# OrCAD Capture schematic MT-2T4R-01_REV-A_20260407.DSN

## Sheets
1 PAGE01.Cheetah PWR: size A3; title: MT-2T4R; rev: A; note: Cheetah PWR
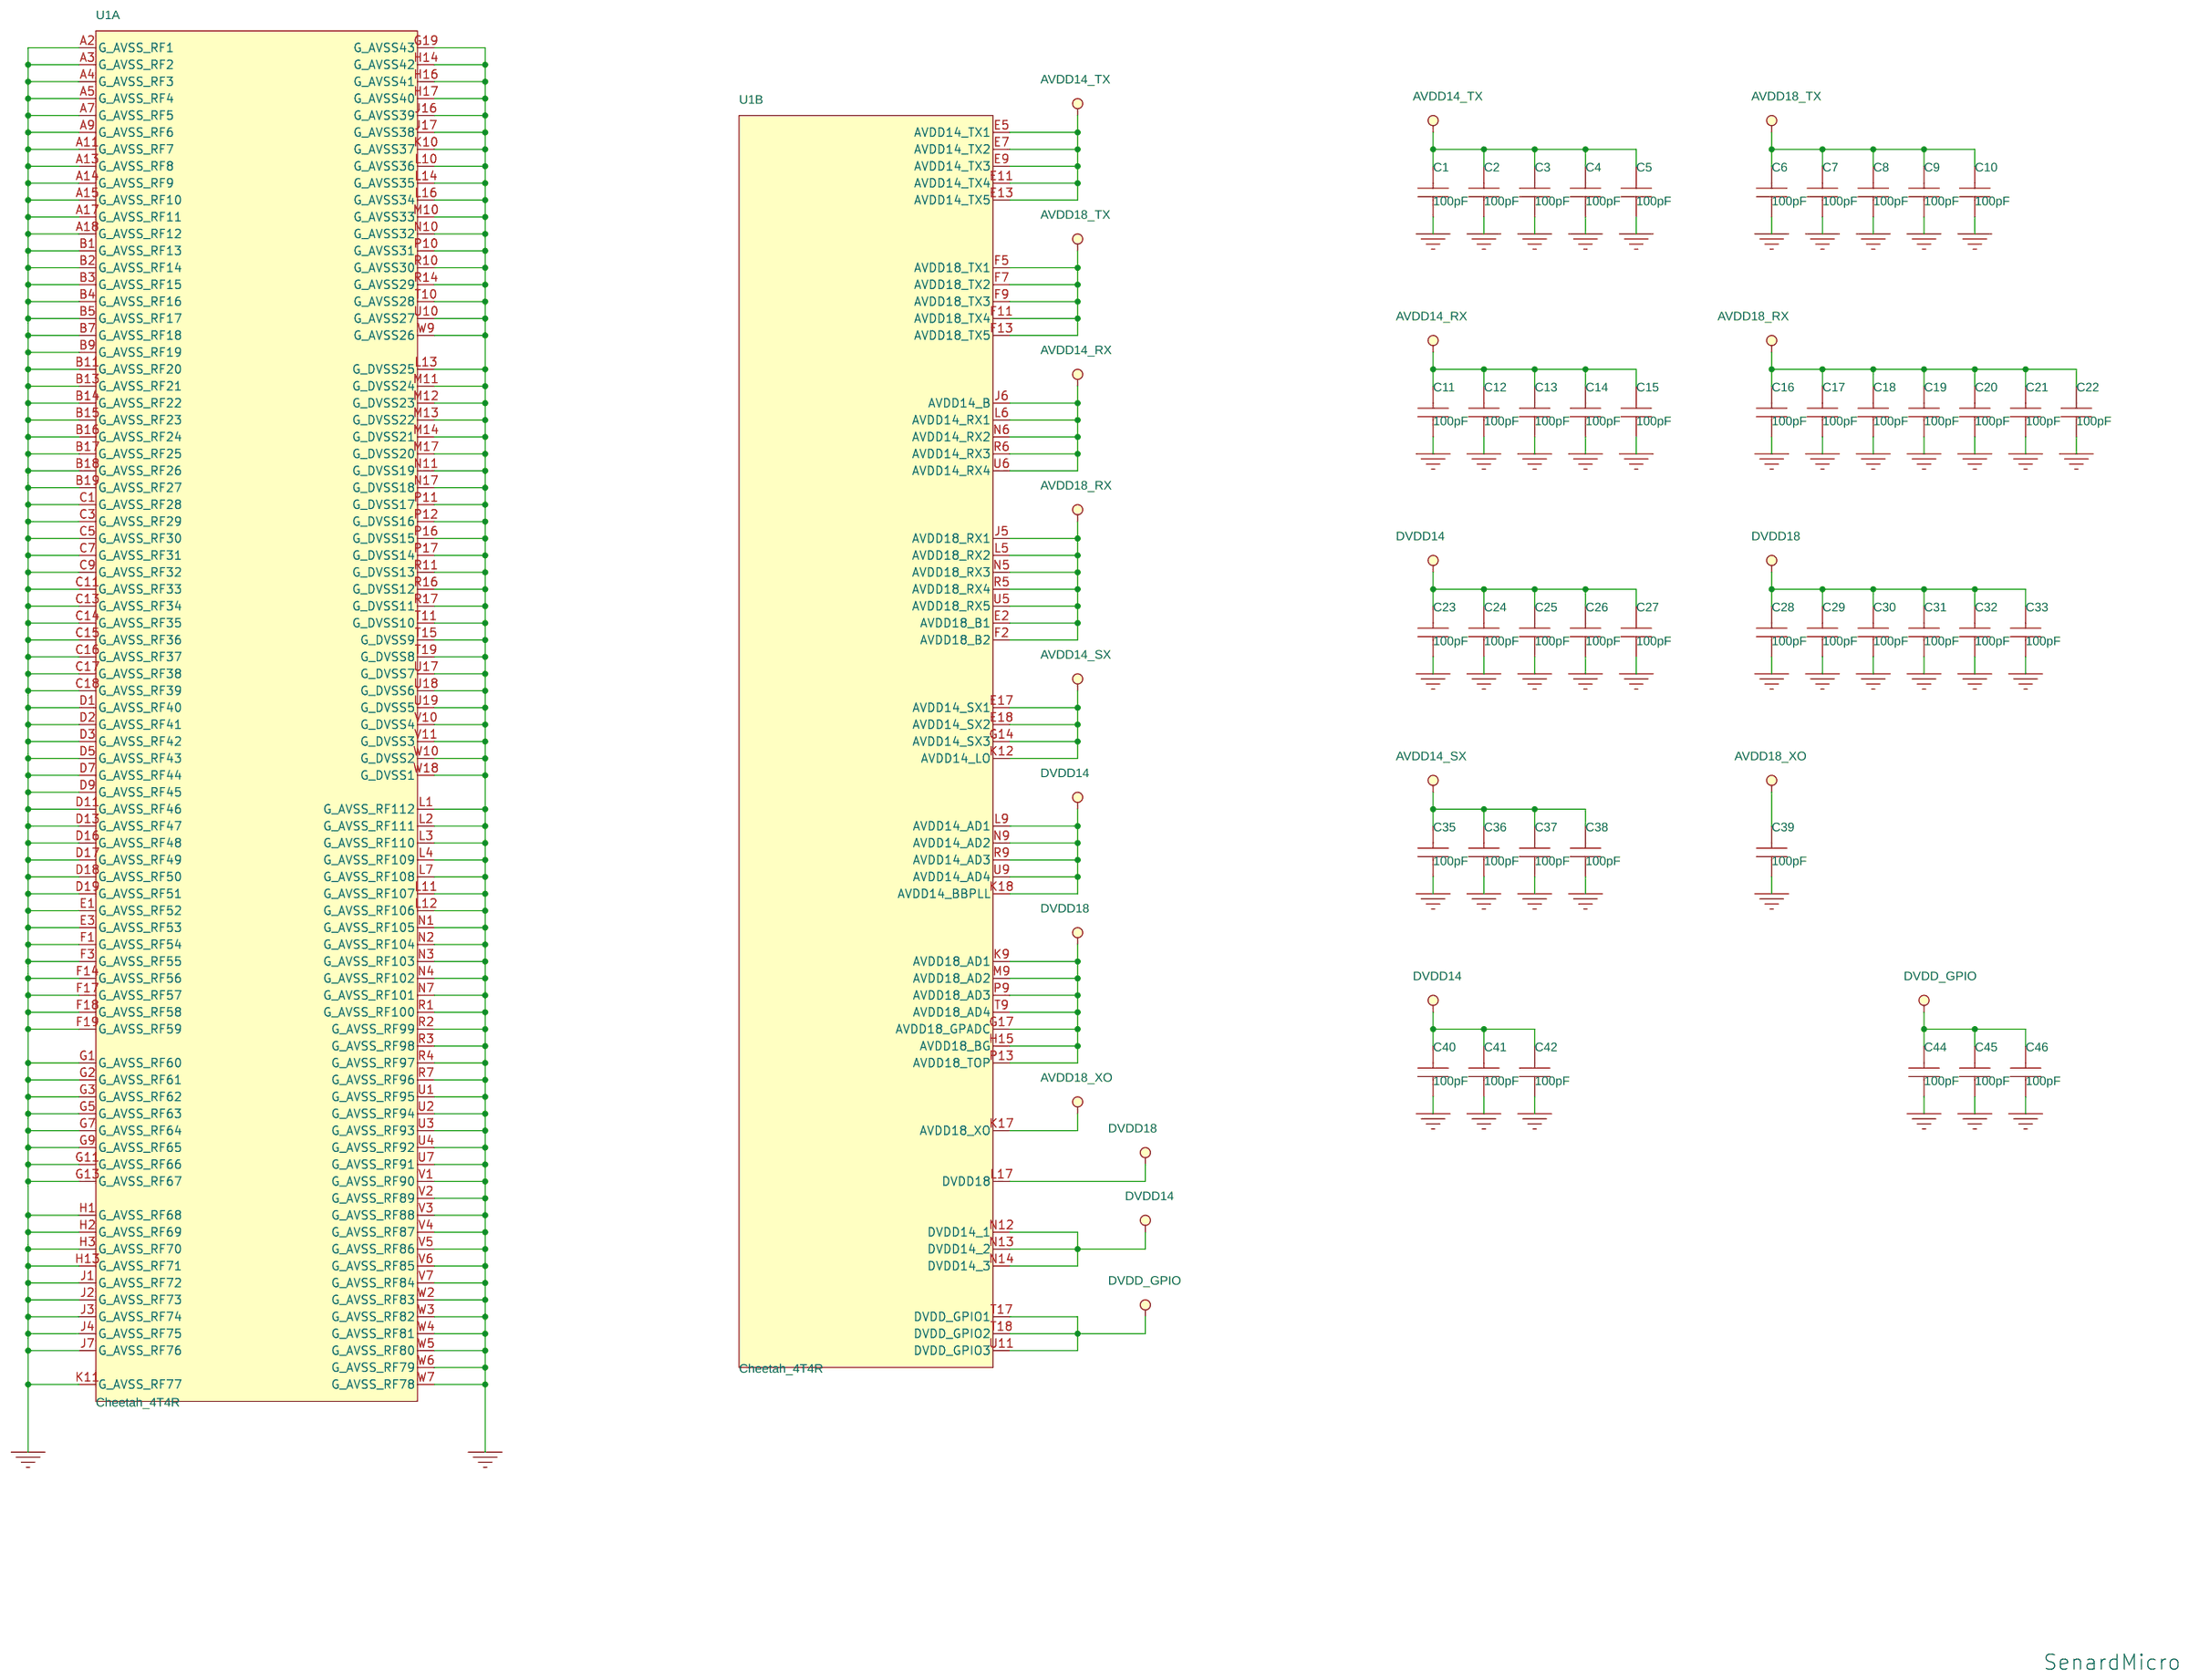
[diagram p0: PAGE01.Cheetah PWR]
2 PAGE02.Cheetah IO: size A3; note: Cheetah IO
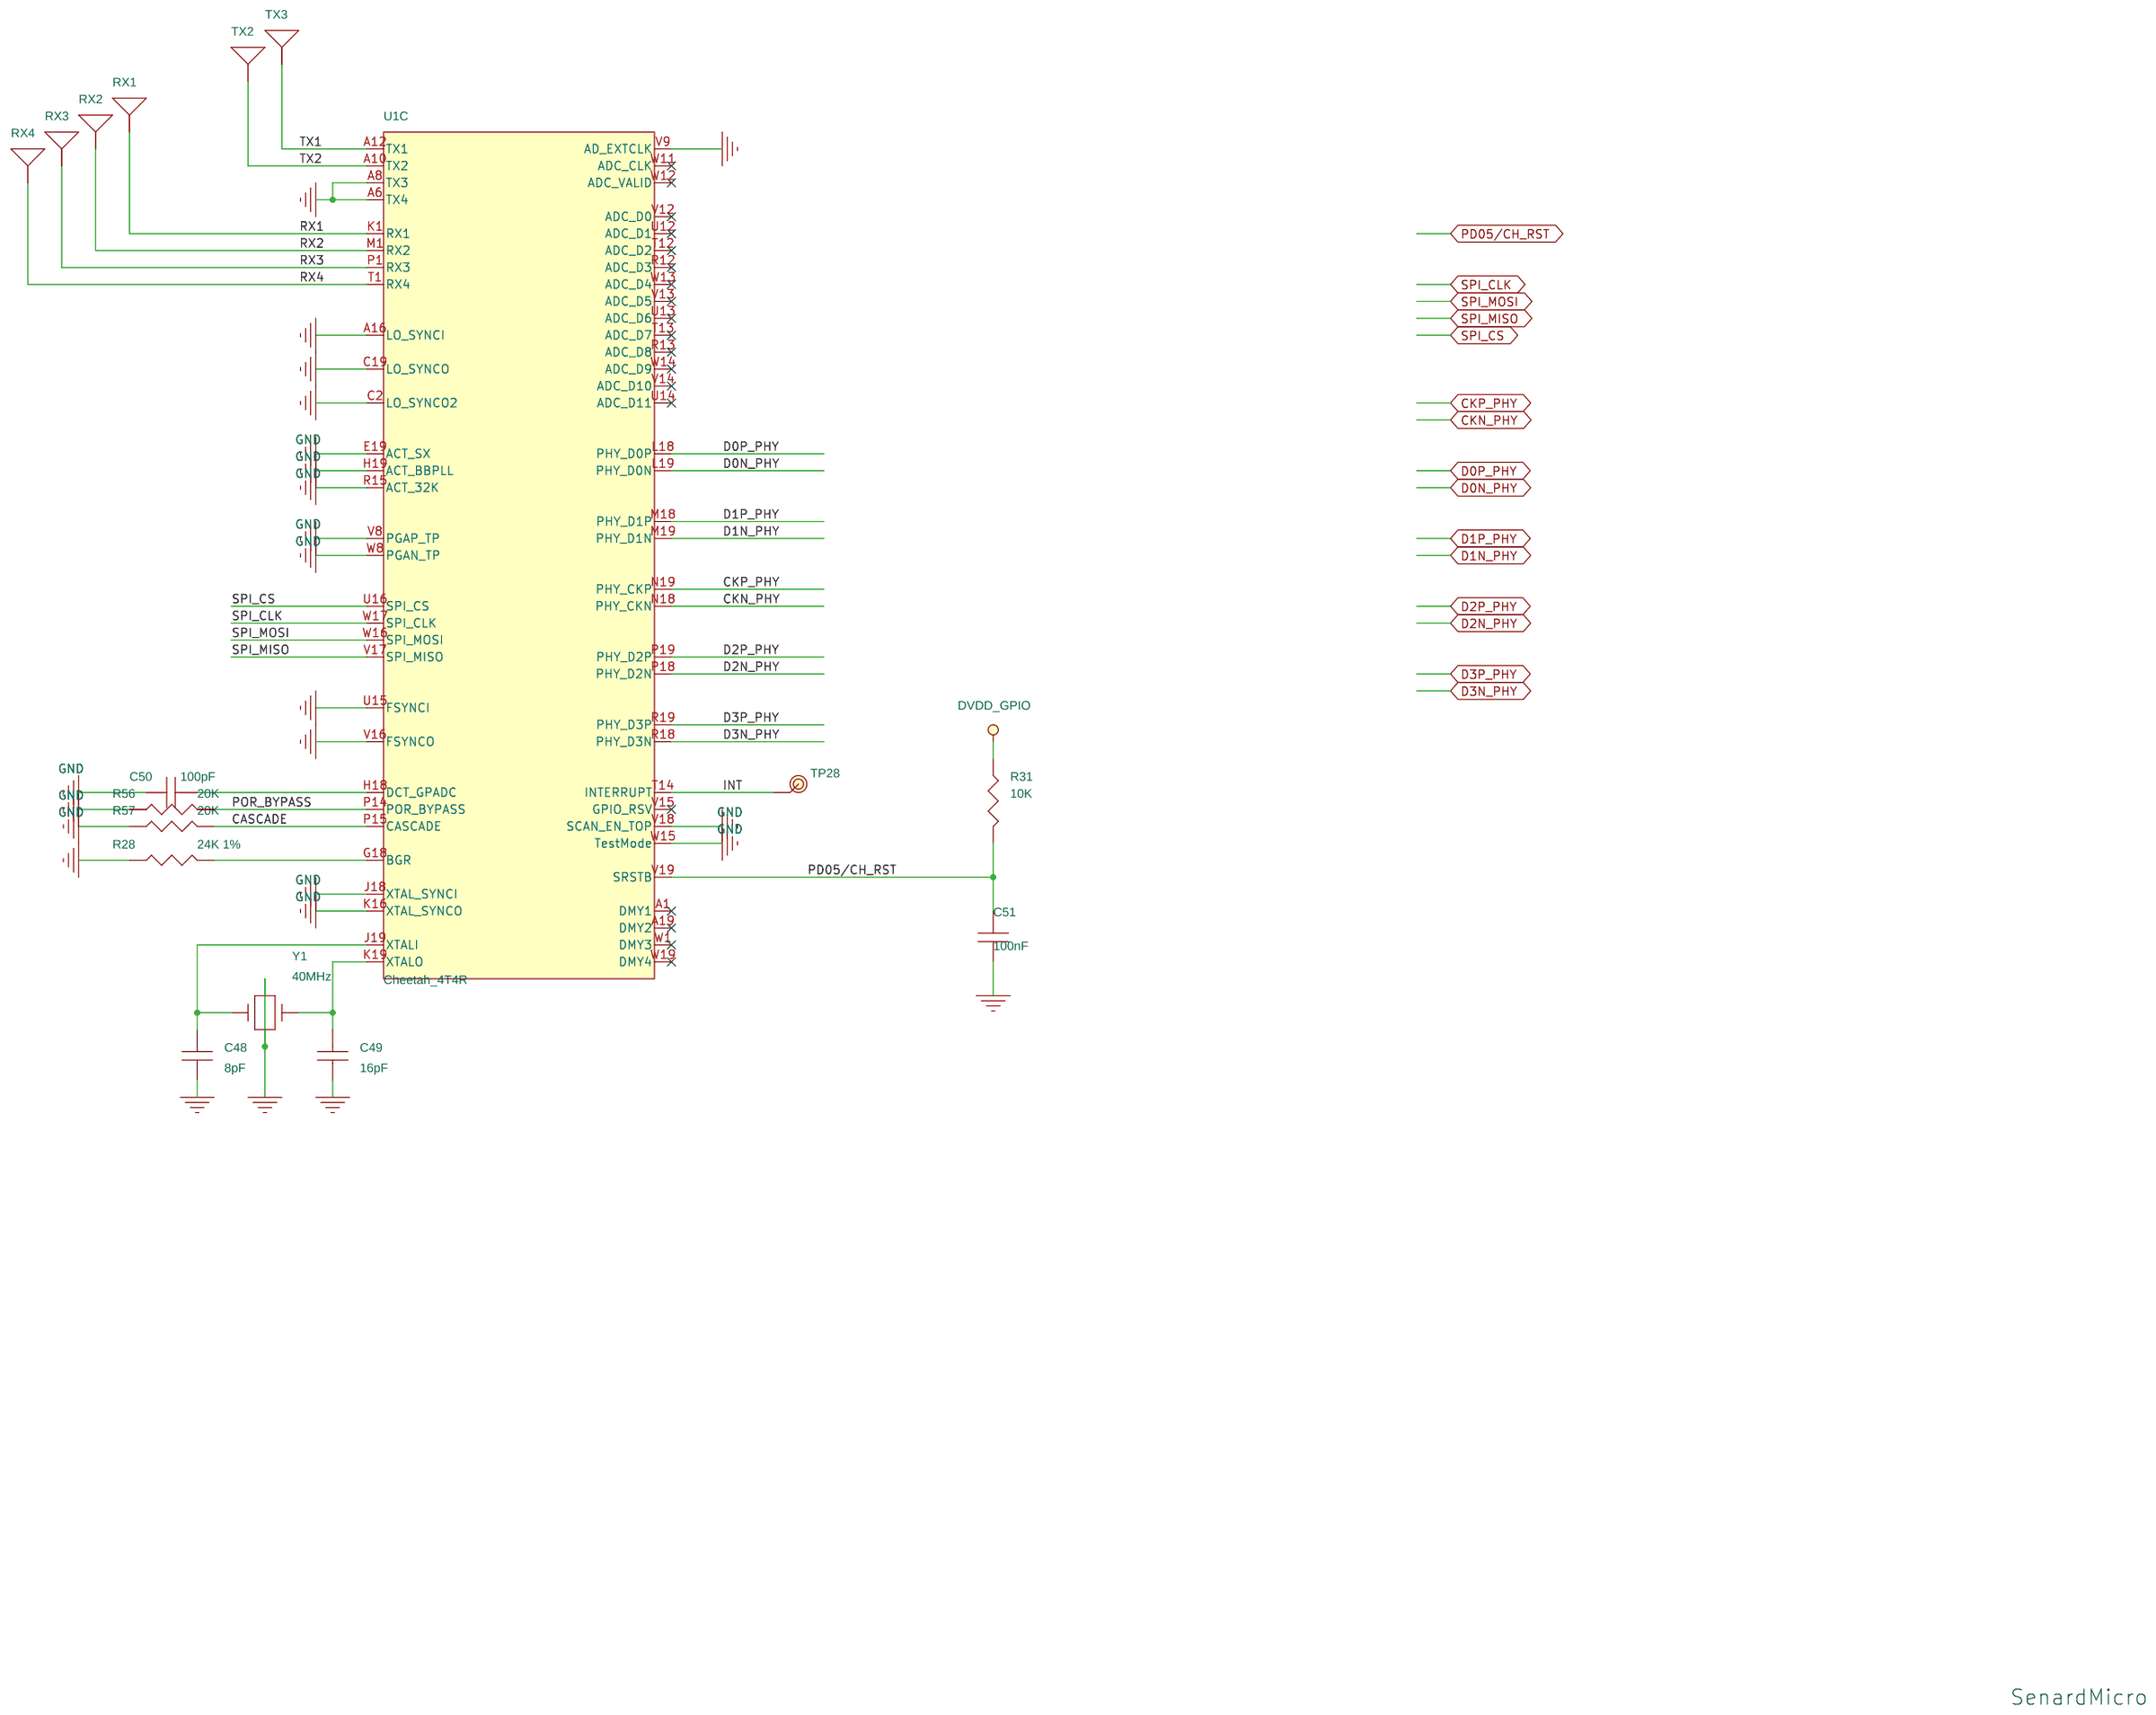
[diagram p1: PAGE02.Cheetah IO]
3 PAGE03.Power Supply: size A3; note: Power Supply
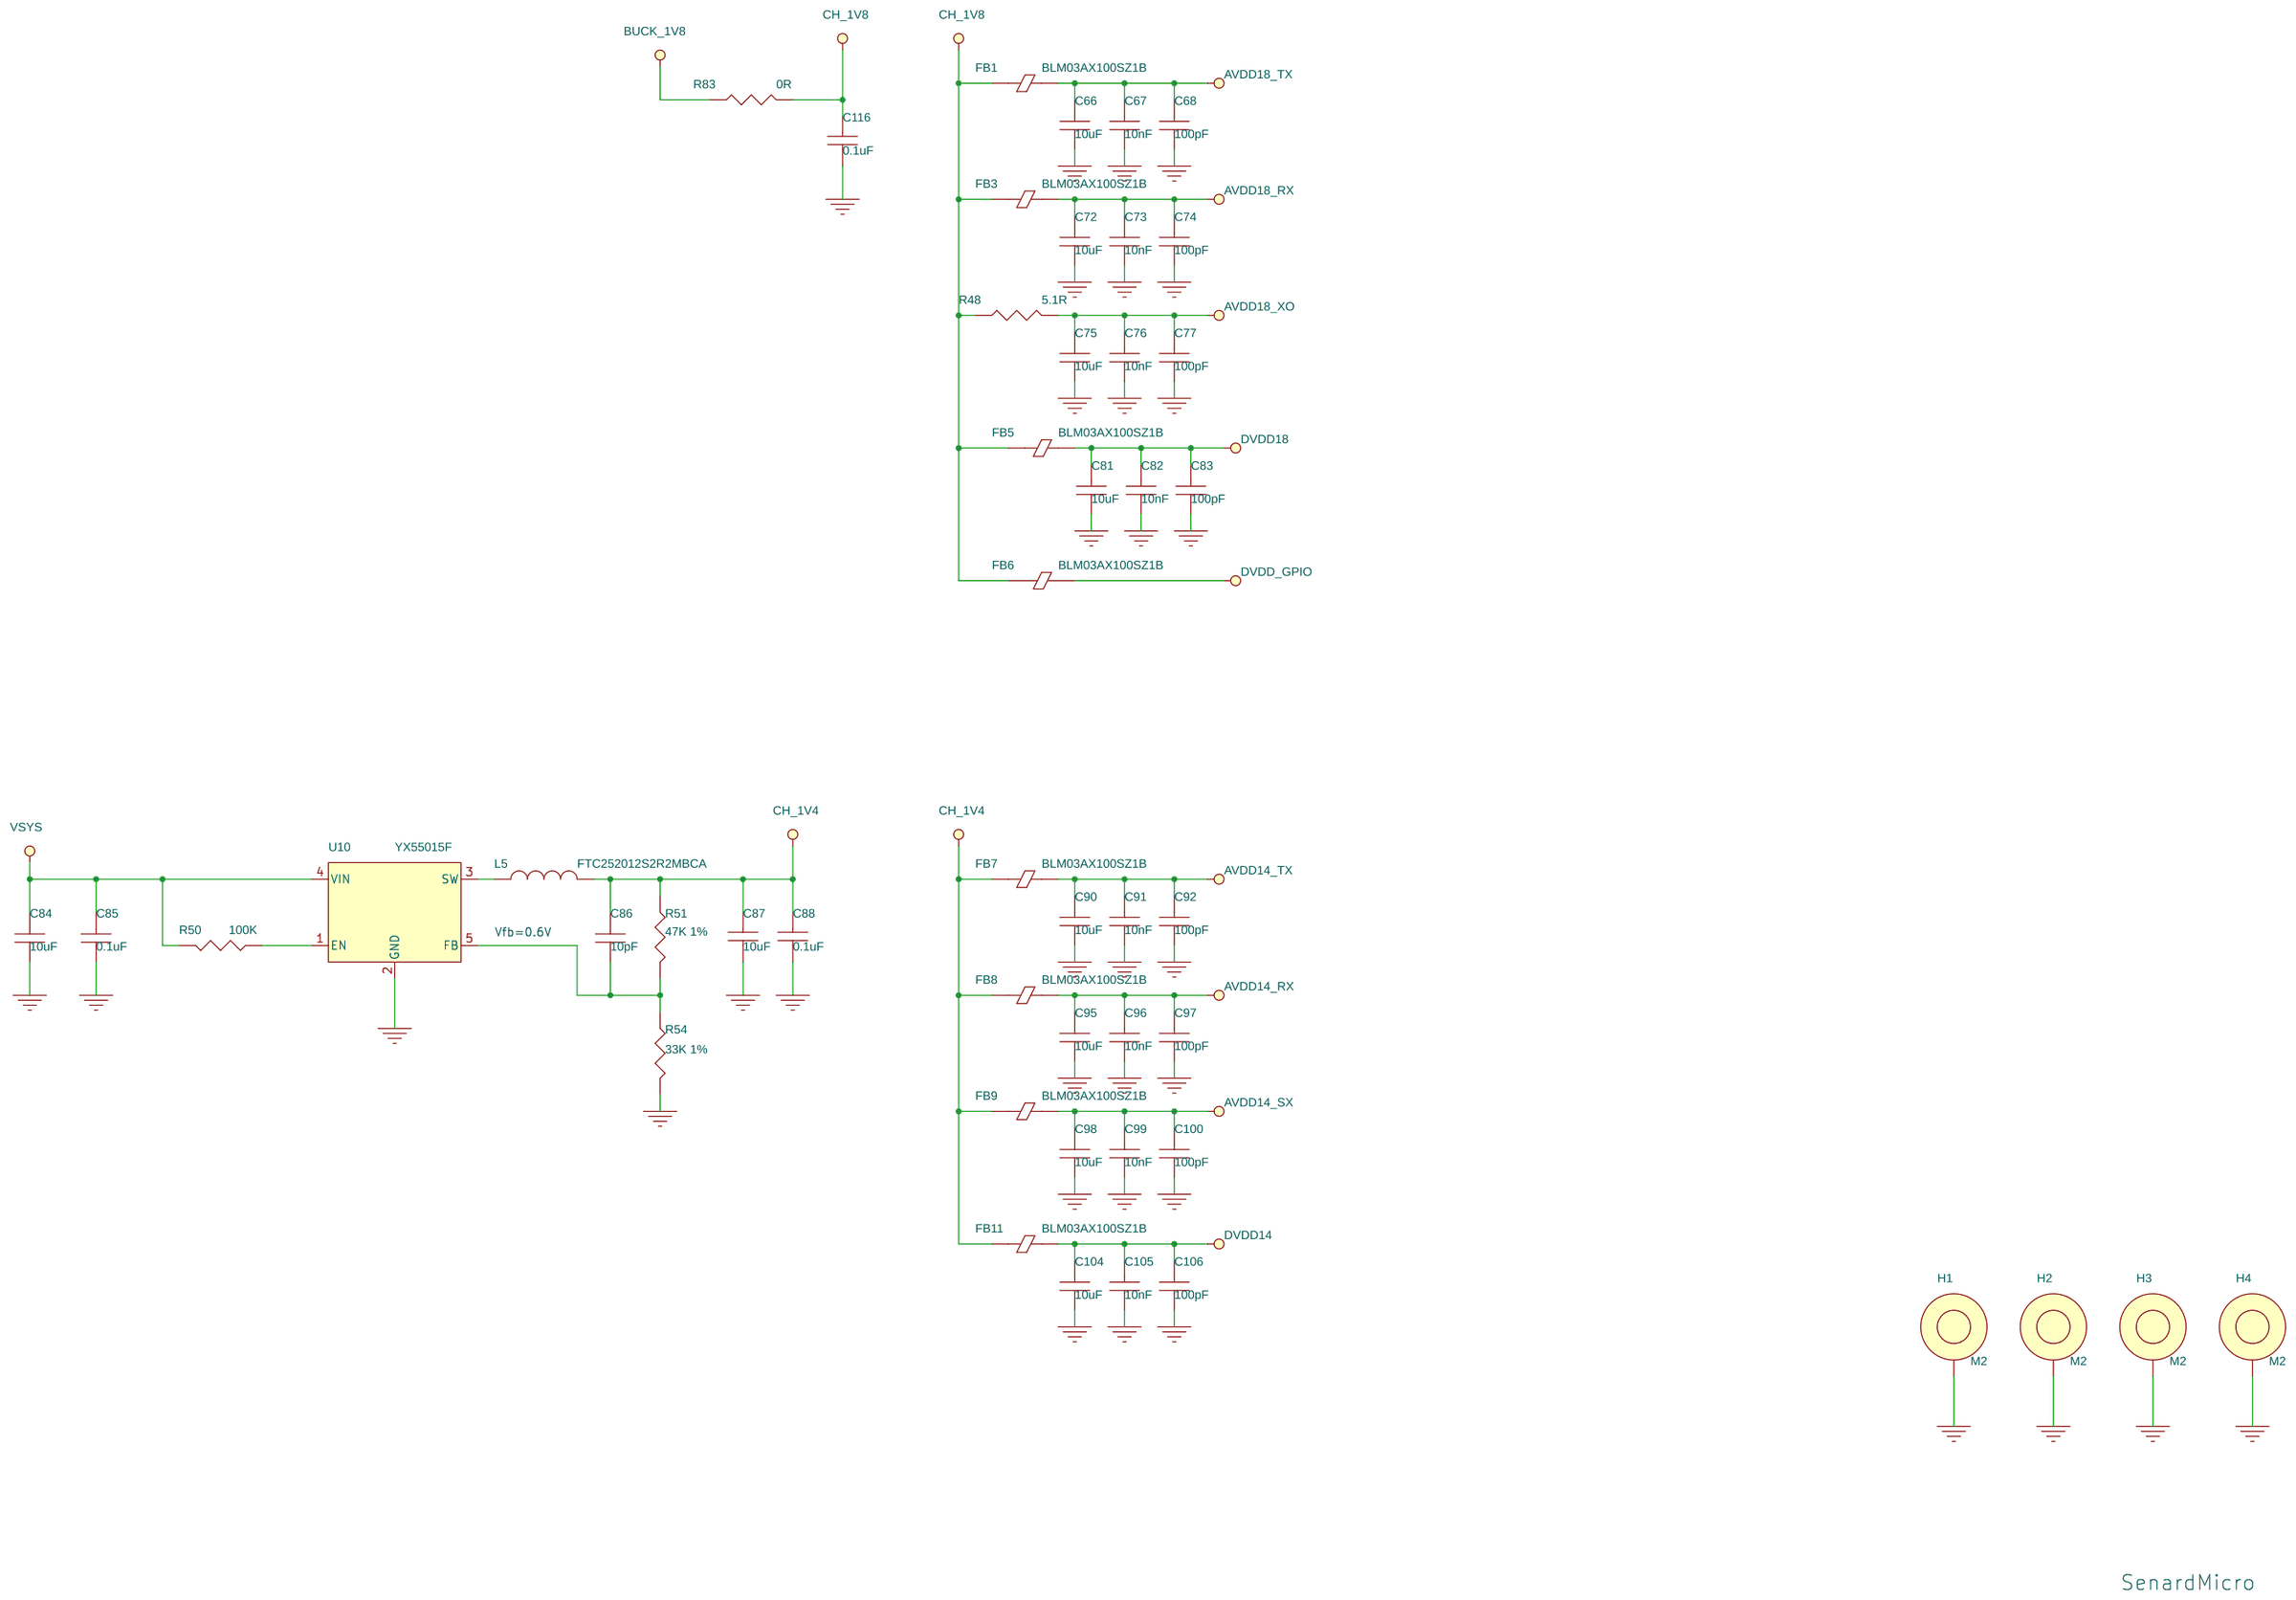
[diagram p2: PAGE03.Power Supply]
4 PAGE05.X2100A/D: size A3; note: X2100A/D
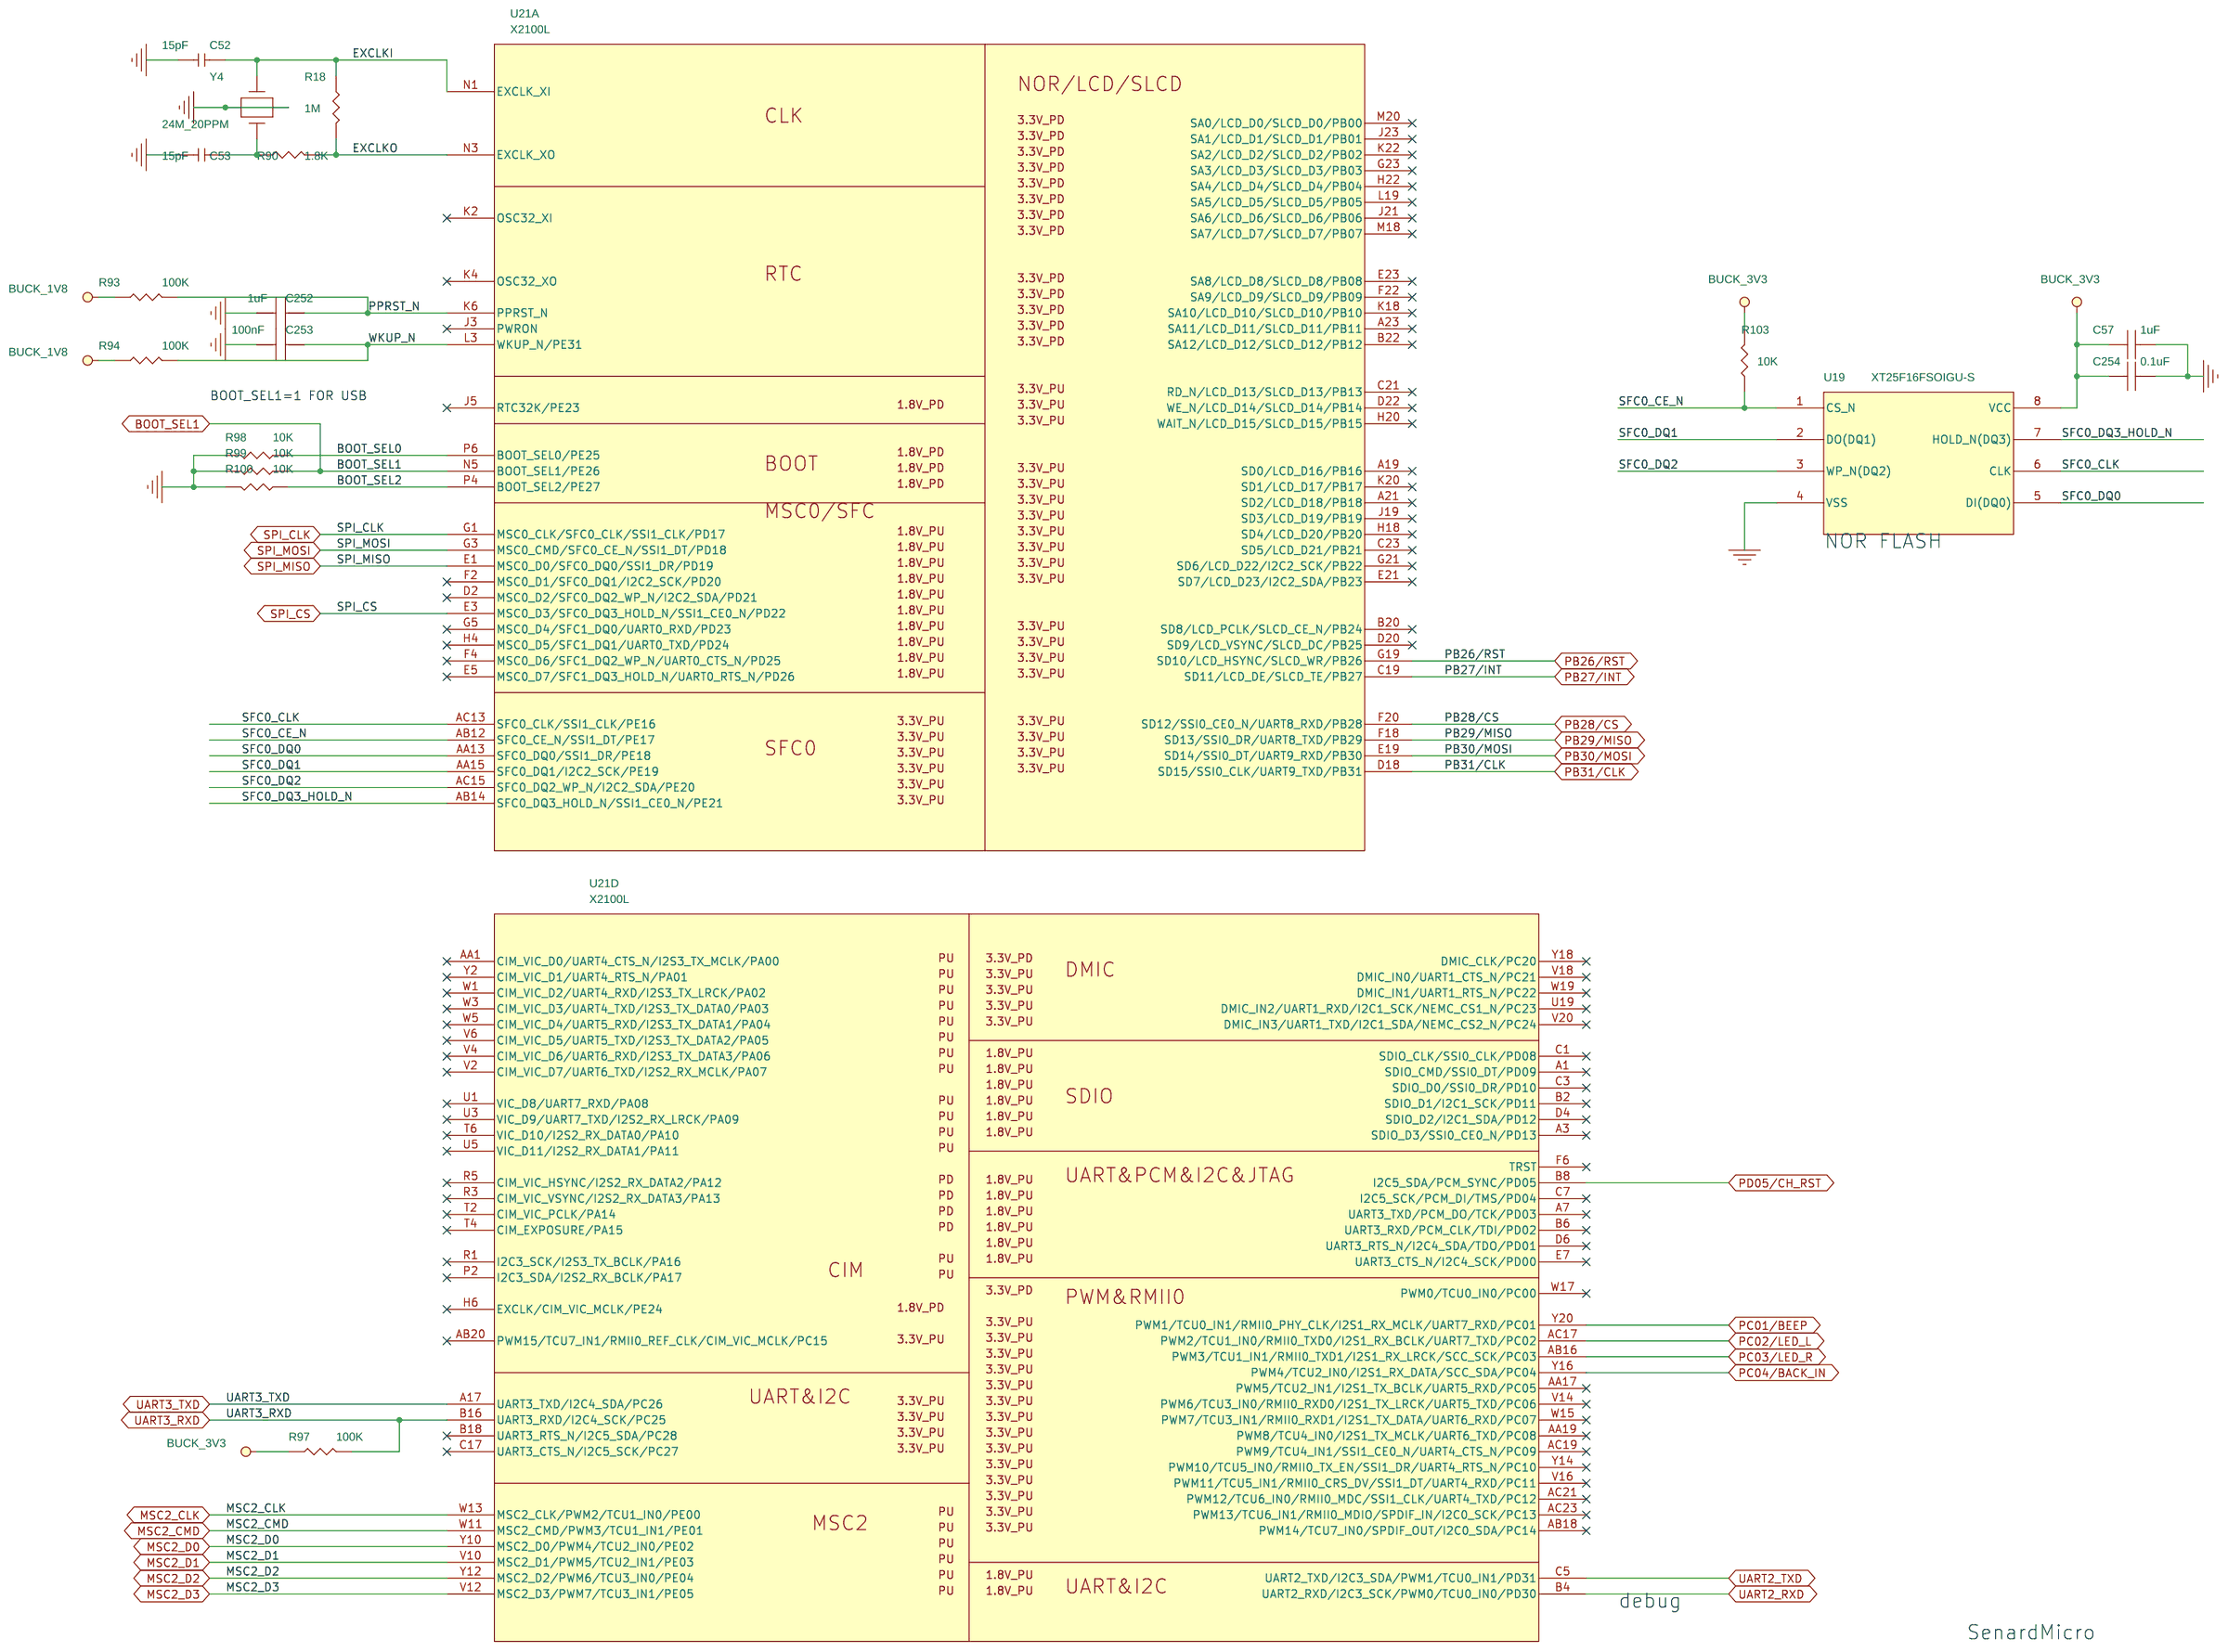
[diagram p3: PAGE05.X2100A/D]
5 PAGE04.X2100B/C: size A3; note: X2100B/C
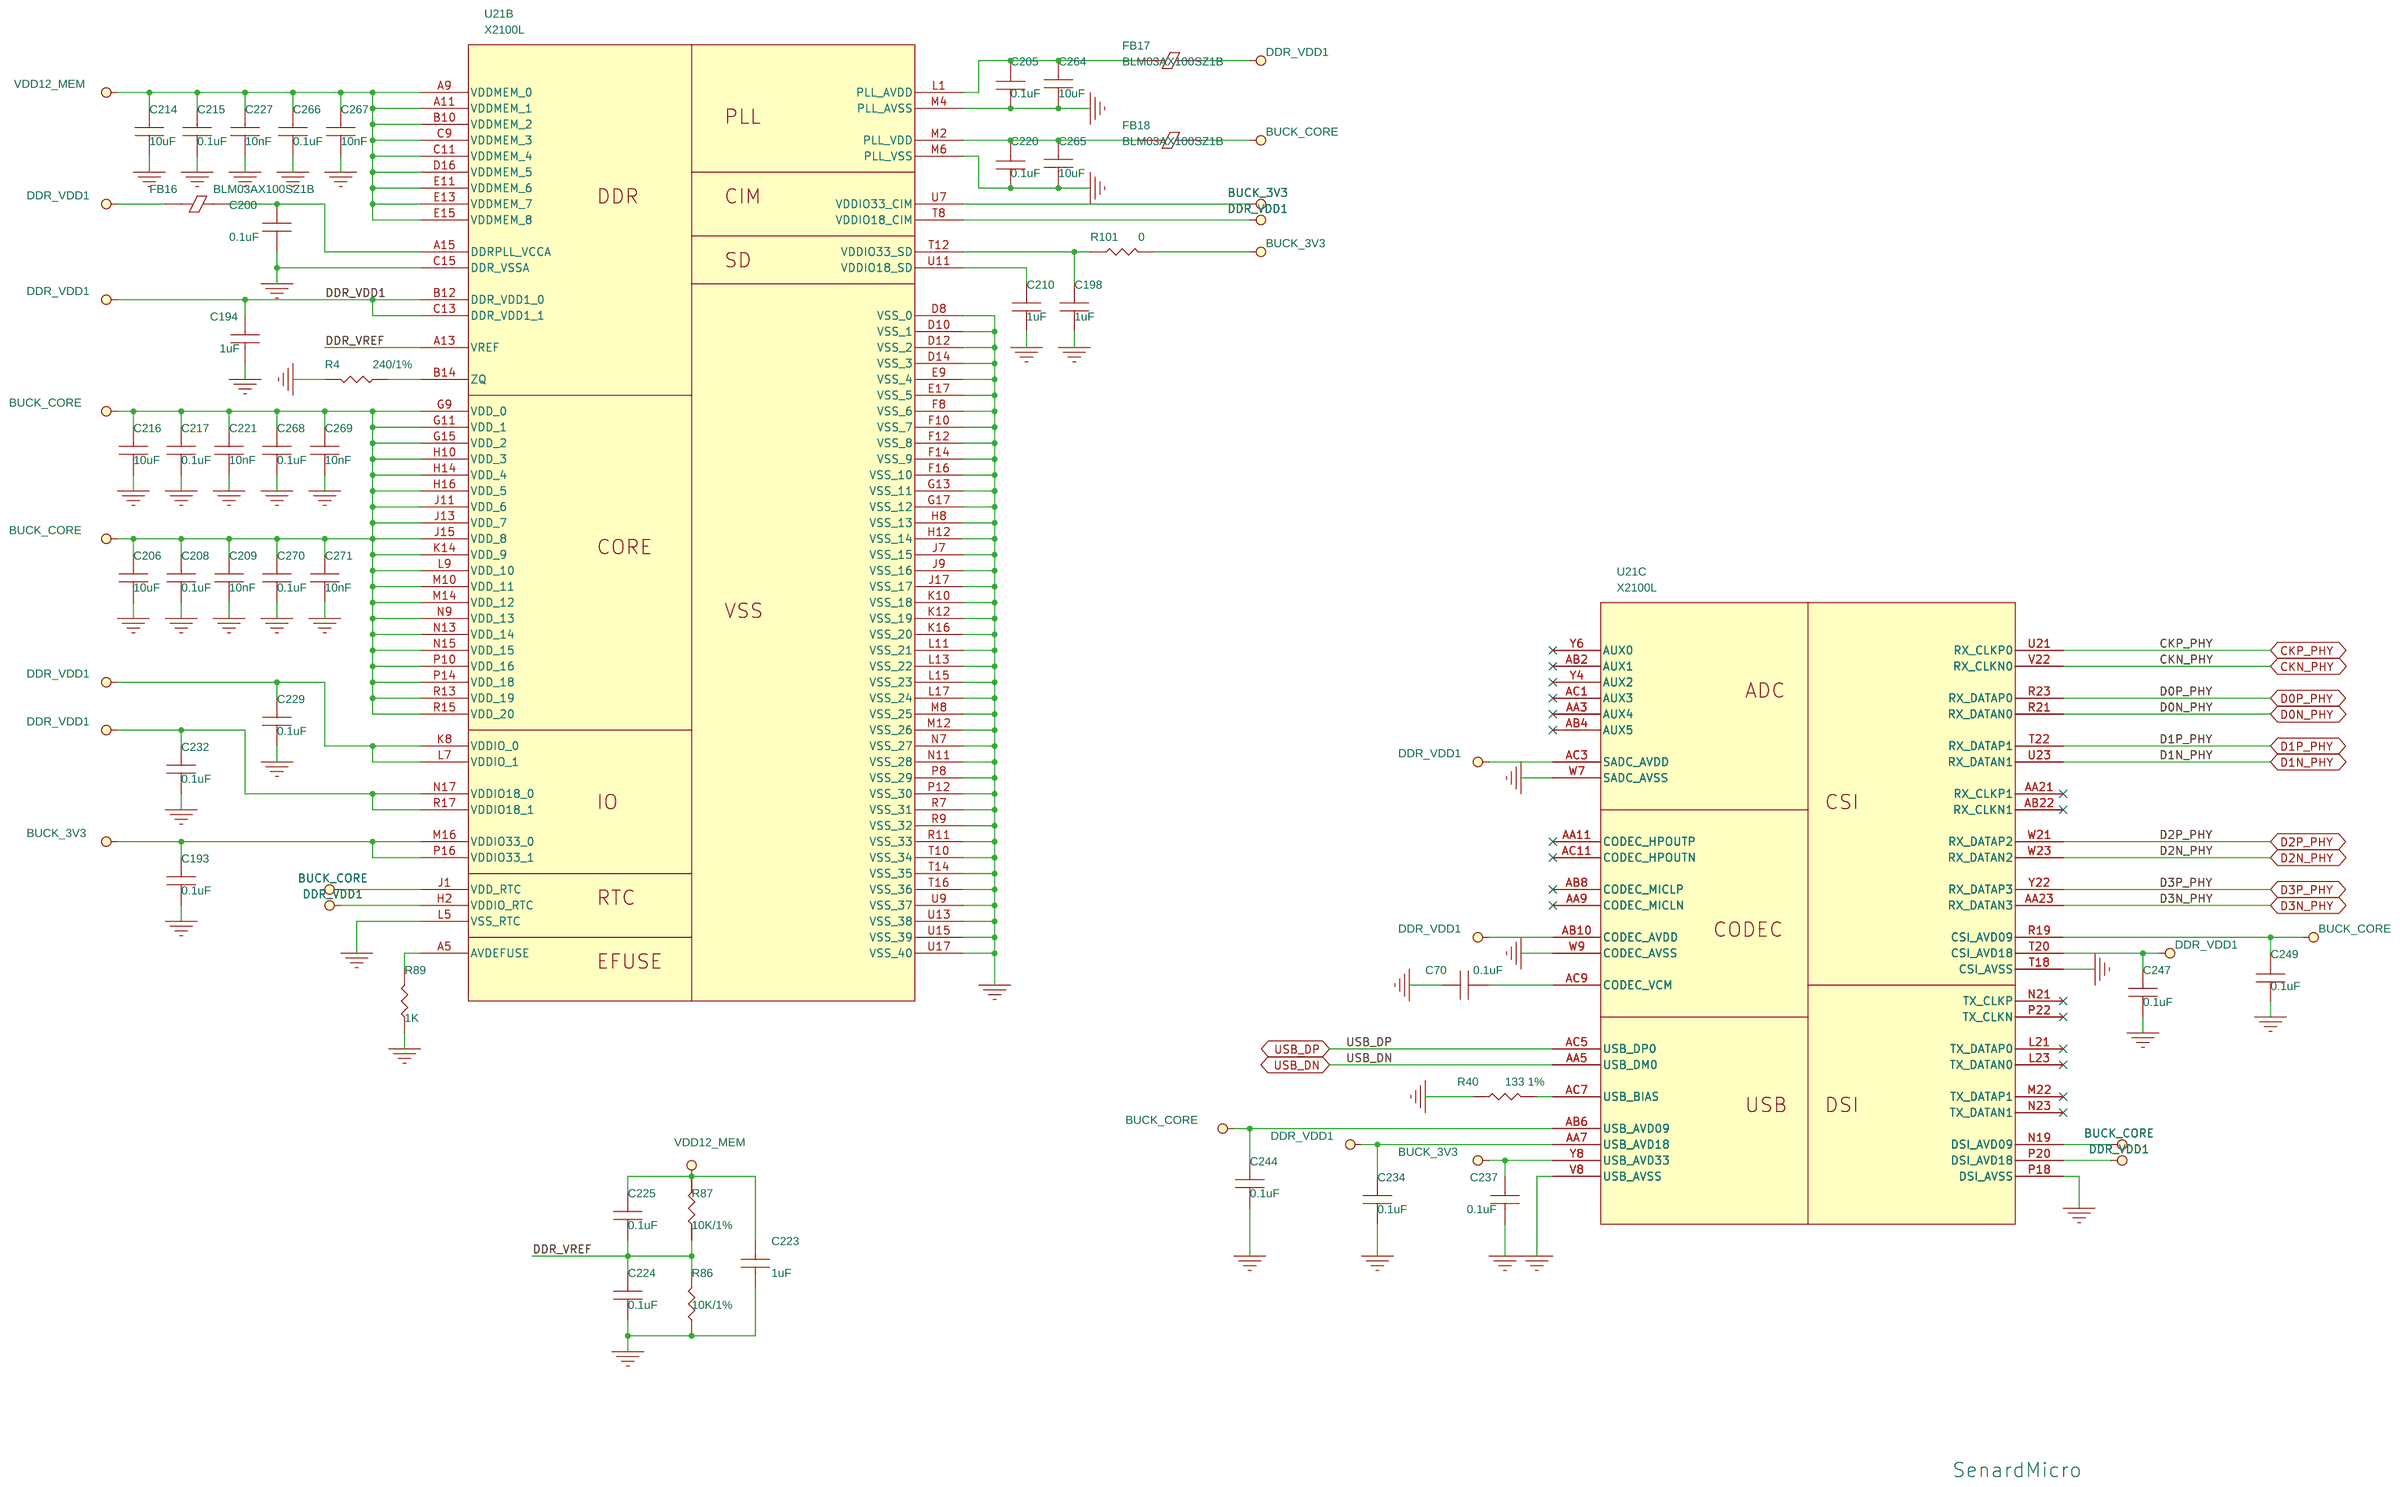
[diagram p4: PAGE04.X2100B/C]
6 PAGE06.POWER/CAN/CON: size A3; note: X2100 PWR/CAN/CON
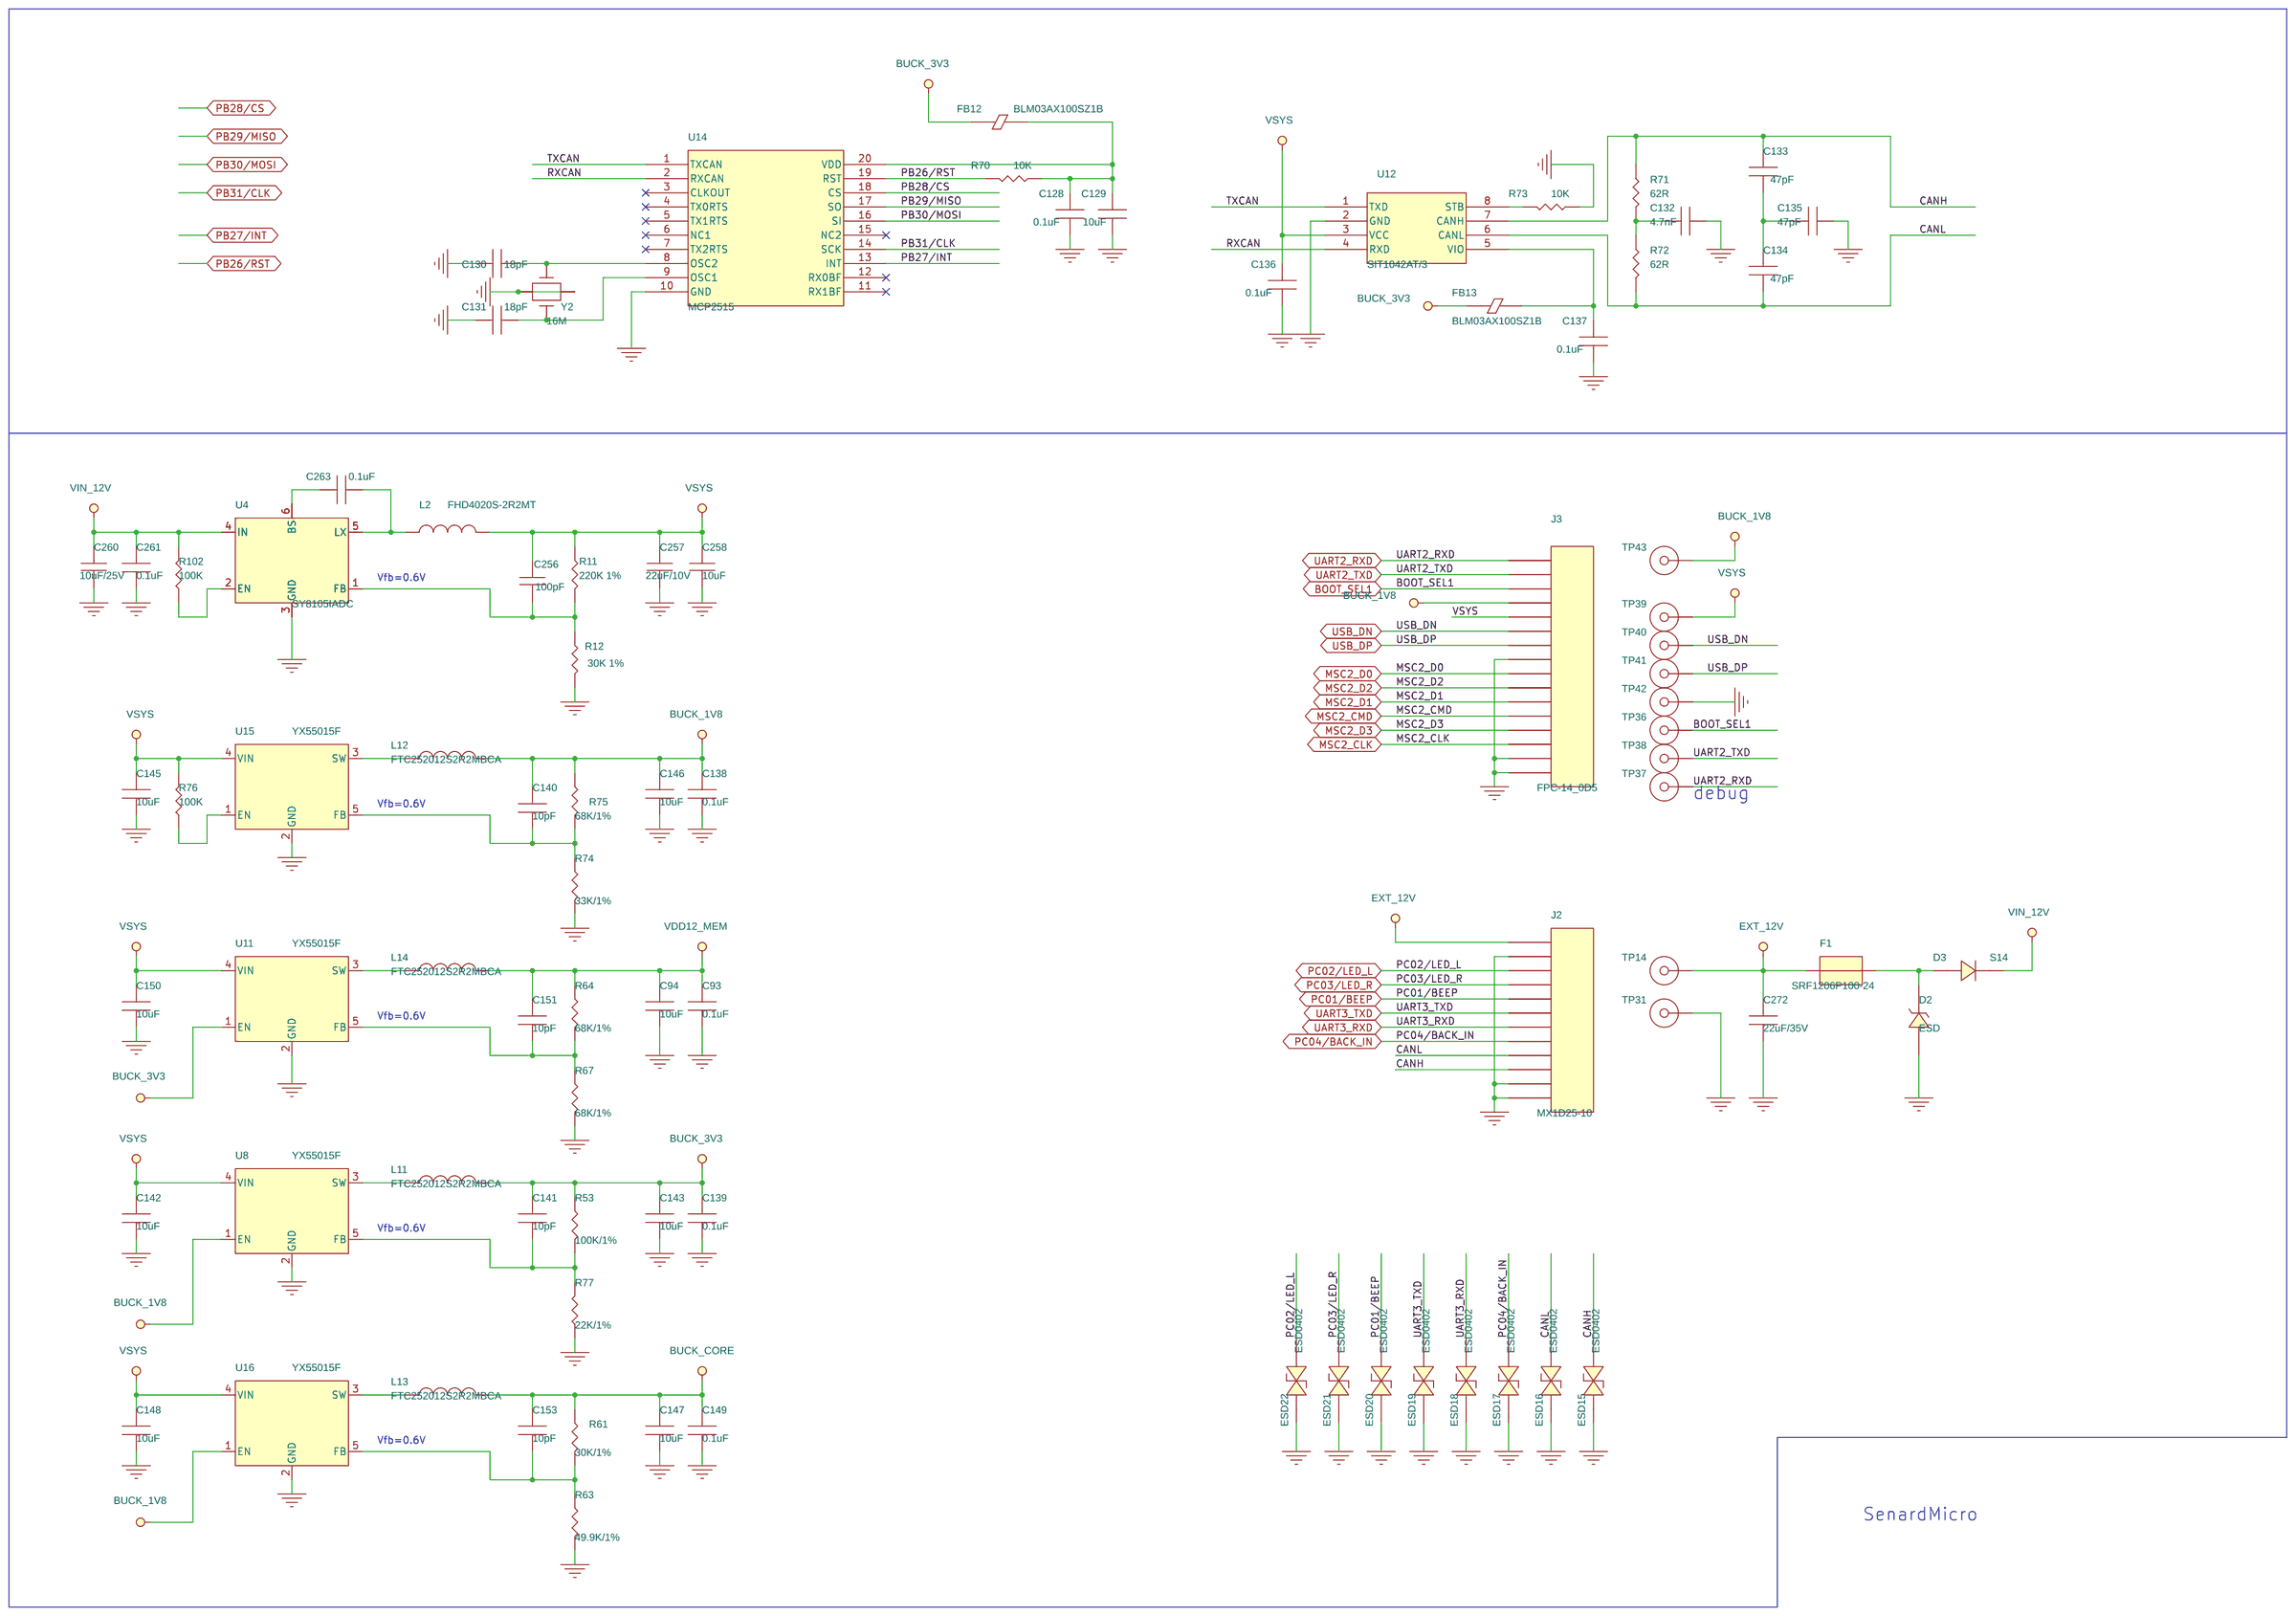
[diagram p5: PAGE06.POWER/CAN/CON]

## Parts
sheet PAGE01.Cheetah PWR
C1  100pF  [0201]
C2  100pF  [0201]
C3  100pF  [0201]
C4  100pF  [0201]
C5  100pF  [0201]
C6  100pF  [0201]
C7  100pF  [0201]
C8  100pF  [0201]
C9  100pF  [0201]
C10  100pF  [0201]
C11  100pF  [0201]
C12  100pF  [0201]
C13  100pF  [0201]
C14  100pF  [0201]
C15  100pF  [0201]
C16  100pF  [0201]
C17  100pF  [0201]
C18  100pF  [0201]
C19  100pF  [0201]
C20  100pF  [0201]
C21  100pF  [0201]
C22  100pF  [0201]
C23  100pF  [0201]
C24  100pF  [0201]
C25  100pF  [0201]
C26  100pF  [0201]
C27  100pF  [0201]
C28  100pF  [0201]
C29  100pF  [0201]
C30  100pF  [0201]
C31  100pF  [0201]
C32  100pF  [0201]
C33  100pF  [0201]
C35  100pF  [0201]
C36  100pF  [0201]
C37  100pF  [0201]
C38  100pF  [0201]
C39  100pF  [0201]
C40  100pF  [0201]
C41  100pF  [0201]
C42  100pF  [0201]
C44  100pF  [0201]
C45  100pF  [0201]
C46  100pF  [0201]
U1  Cheetah_4T4R  [Cheetah_WLCSP265]  (sections A,B,C)
sheet PAGE02.Cheetah IO
C48  8pF  [0201]
C49  16pF  [0201]
C50  100pF  [0201]
C51  100nF  [0201]
R28  24K 1%  [0201]
R31  10K  [0201]
R56  20K  [0201]
R57  20K  [0201]
RX1  ANTENNA  [MOTO_1X4_RF]
RX2  ANTENNA  [MOTO_1X4_RF]
RX3  ANTENNA  [MOTO_1X4_RF]
RX4  ANTENNA  [MOTO_1X4_RF]
TP28  T  [TP_60]
TX2  ANTENNA  [MOTO_1X4_RF]
TX3  ANTENNA  [MOTO_1X4_RF]
Y1  40MHz  [CRY4_2016]
sheet PAGE03.Power Supply
C66  10uF  [C0402]
C67  10nF  [C0402]
C68  100pF  [C0402]
C72  10uF  [C0402]
C73  10nF  [C0402]
C74  100pF  [C0402]
C75  10uF  [C0402]
C76  10nF  [C0402]
C77  100pF  [C0402]
C81  10uF  [C0402]
C82  10nF  [C0402]
C83  100pF  [C0402]
C84  10uF  [C0402]
C85  0.1uF  [C0402]
C86  10pF  [C0402]
C87  10uF  [C0402]
C88  0.1uF  [C0402]
C90  10uF  [C0402]
C91  10nF  [C0402]
C92  100pF  [C0402]
C95  10uF  [C0402]
C96  10nF  [C0402]
C97  100pF  [C0402]
C98  10uF  [C0402]
C99  10nF  [C0402]
C100  100pF  [C0402]
C104  10uF  [C0402]
C105  10nF  [C0402]
C106  100pF  [C0402]
C116  0.1uF  [C0402]
FB1  BLM03AX100SZ1B  [L0402]
FB3  BLM03AX100SZ1B  [L0402]
FB5  BLM03AX100SZ1B  [L0402]
FB6  BLM03AX100SZ1B  [L0402]
FB7  BLM03AX100SZ1B  [L0402]
FB8  BLM03AX100SZ1B  [L0402]
FB9  BLM03AX100SZ1B  [L0402]
FB11  BLM03AX100SZ1B  [L0402]
H1  M2  [MH3D2-2D0]
H2  M2  [MH3D2-2D0]
H3  M2  [MH3D2-2D0]
H4  M2  [MH3D2-2D0]
L5  FTC252012S2R2MBCA  [L2520]
R48  5.1R  [R0402]
R50  100K  [R0402]
R51  47K 1%  [R0402]
R54  33K 1%  [R0402]
R83  0R  [R0603]
U10  YX55015F  [SOT23-5L]
sheet PAGE04.X2100B/C
C70  0.1uF  [C0402]
C193  0.1uF  [C0402]
C194  1uF  [C0402]
C198  1uF  [C0402]
C200  0.1uF  [C0402]
C205  0.1uF  [C0402]
C206  10uF  [C0402]
C208  0.1uF  [C0402]
C209  10nF  [C0402]
C210  1uF  [C0402]
C214  10uF  [C0402]
C215  0.1uF  [C0402]
C216  10uF  [C0402]
C217  0.1uF  [C0402]
C220  0.1uF  [C0402]
C221  10nF  [C0402]
C223  1uF  [C0402]
C224  0.1uF  [C0402]
C225  0.1uF  [C0402]
C227  10nF  [C0402]
C229  0.1uF  [C0402]
C232  0.1uF  [C0402]
C234  0.1uF  [C0402]
C237  0.1uF  [C0402]
C244  0.1uF  [C0402]
C247  0.1uF  [C0402]
C249  0.1uF  [C0402]
C264  10uF  [C0402]
C265  10uF  [C0402]
C266  0.1uF  [C0402]
C267  10nF  [C0402]
C268  0.1uF  [C0402]
C269  10nF  [C0402]
C270  0.1uF  [C0402]
C271  10nF  [C0402]
FB16  BLM03AX100SZ1B  [L0402]
FB17  BLM03AX100SZ1B  [L0402]
FB18  BLM03AX100SZ1B  [L0402]
R4  240/1%  [R0402]
R40  133 1%  [R0402]
R86  10K/1%  [R0402]
R87  10K/1%  [R0402]
R89  1K  [R0402]
R101  0  [R0402]
U21  X2100L  [X2100_BGA264_0D43_10X10]  (sections A,B,C,D)
sheet PAGE05.X2100A/D
C52  15pF  [C0402]
C53  15pF  [C0402]
C57  1uF  [C0402]
C252  1uF  [C0402]
C253  100nF  [0201]
C254  0.1uF  [C0402]
R18  1M  [R0402]
R90  1.8K  [R0402]
R93  100K  [R0402]
R94  100K  [R0402]
R97  100K  [R0402]
R98  10K  [R0402]
R99  10K  [R0402]
R100  10K  [R0402]
R103  10K  [R0402]
U19  XT25F16FSOIGU-S  [SOP-8]
Y4  24M_20PPM  [CRY4_2016]
sheet PAGE06.POWER/CAN/CON
C93  0.1uF  [C0402]
C94  10uF  [C0402]
C128  0.1uF  [C0402]
C129  10uF  [C0402]
C130  18pF  [C0402]
C131  18pF  [C0402]
C132  4.7nF  [C0402]
C133  47pF  [C0402]
C134  47pF  [C0402]
C135  47pF  [C0402]
C136  0.1uF  [C0402]
C137  0.1uF  [C0402]
C138  0.1uF  [C0402]
C139  0.1uF  [C0402]
C140  10pF  [C0402]
C141  10pF  [C0402]
C142  10uF  [C0402]
C143  10uF  [C0402]
C145  10uF  [C0402]
C146  10uF  [C0402]
C147  10uF  [C0402]
C148  10uF  [C0402]
C149  0.1uF  [C0402]
C150  10uF  [C0402]
C151  10pF  [C0402]
C153  10pF  [C0402]
C256  100pF  [C0402]
C257  22uF/10V  [C0805]
C258  10uF  [C0402]
C260  10uF/25V  [C0603]
C261  0.1uF  [C0402]
C263  0.1uF  [C0402]
C272  22uF/35V  [C1210]
D2  ESD  [SOD123_FL]
D3  S14  [SOD123_FL]
ESD15  ESD0402  [ESD0402]
ESD16  ESD0402  [ESD0402]
ESD17  ESD0402  [ESD0402]
ESD18  ESD0402  [ESD0402]
ESD19  ESD0402  [ESD0402]
ESD20  ESD0402  [ESD0402]
ESD21  ESD0402  [ESD0402]
ESD22  ESD0402  [ESD0402]
F1  SRF1206P100-24  [F1206]
FB12  BLM03AX100SZ1B  [L0402]
FB13  BLM03AX100SZ1B  [L0402]
J2  MX1D25-10  [1D25T-10PLT]
J3  FPC-14_0D5  [HC-FPC-05-09-14RLTAG]
L2  FHD4020S-2R2MT  [L4020]
L11  FTC252012S2R2MBCA  [L2520]
L12  FTC252012S2R2MBCA  [L2520]
L13  FTC252012S2R2MBCA  [L2520]
L14  FTC252012S2R2MBCA  [L2520]
R11  220K 1%  [R0402]
R12  30K 1%  [R0402]
R53  100K/1%  [R0402]
R61  30K/1%  [R0402]
R63  49.9K/1%  [R0402]
R64  68K/1%  [R0402]
R67  68K/1%  [R0402]
R70  10K  [R0402]
R71  62R  [R0402]
R72  62R  [R0402]
R73  10K  [R0402]
R74  33K/1%  [R0402]
R75  68K/1%  [R0402]
R76  100K  [R0402]
R77  22K/1%  [R0402]
R102  100K  [R0402]
TP14  NC  [TP_80]
TP31  NC  [TP_80]
TP36  NC  [TP_80]
TP37  NC  [TP_80]
TP38  NC  [TP_80]
TP39  NC  [TP_80]
TP40  NC  [TP_80]
TP41  NC  [TP_80]
TP42  NC  [TP_80]
TP43  NC  [TP_80]
U4  SY8105IADC  [SOT23-6]
U8  YX55015F  [SOT23-5L]
U11  YX55015F  [SOT23-5L]
U12  SIT1042AT/3  [SOP-8]
U14  MCP2515  [TSSOP20]
U15  YX55015F  [SOT23-5L]
U16  YX55015F  [SOT23-5L]
Y2  16M  [CRY4_2016]

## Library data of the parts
C1-C33 C35-C42 C44-C46 C51 C66-C68 C72-C77 C81-C86 C90-C92 C95-C100 C104-C106 = CAP_NP: CAP X7S 0.1μF ±20 50V 0402; Part: GRM155C71H104ME19D; Vendor: Murata
U1 = Cheetah_4T4R
C48-C50 = CAP_NP: CAP CER 4.7pF ±0.1pF 50V  C0G  0402; AGILE_PN: 150-79813; CAD_APPROVED: Yes; FPLIST: CC0201,CC0201_HD,0201_CC; HEIGHT: 0.33MM; MFG_NAME01: TDK; MFG_PN01: CGA1A2C0G1E120J030BA; Part: GJM1555C1H4R7BB01D; ROHS: Yes; Tolerance: 5%; VOLTAGE: 25V; Vendor: Murata
R28 R48 R50 R56 R57 = RES_0: RES 1/10W 10K 0.1% 0402; AGILE_PN: 470-75394; CAD_APPROVED: Yes; FPLIST: RC0402_25,RC0402_HD,RC0402_X2,0402_CC; HEIGHT: 0.45 MM; MFG_NAME01: ROHM; MFG_PN01: MCR01MZPJ000; Part: RC0402BR-0710KL; ROHS: Yes; Tolerance: 5%; Vendor: Yageo
R31 R51 = R: RES 1/16W 475K 0.1% 0402; Part: RC0402BR-07475KL; Vendor: Yageo
RX1-RX4 TX2 TX3 = ANTENNA_2
TP28 = TEST_2: 1ST PART DESCRIPTION: TESTPOINT
Y1 = CRYSTAL_4: 1ST PART DESCRIPTION: HOSONIC E3SB48.0000F12E11 48MHz Crystal 12pF load capacitance
C87 C88 C116 = CAP_NP: 1ST PART DESCRIPTION: CAP 22uF X7R 6.3V 20%; Pin Names Rotate: True; Pin Names Visible: False; Pin Numbers Visible: False
FB1 FB3 FB5-FB9 FB11-FB13 = FB: 1ST PART DESCRIPTION: Ferrite Bead Z=120@100MHz 20%
H1-H4 = HOLE-V8_3: MH7-3.2-7
L5 = Inductor_1206_H_0
R54 R83 = R: RES 1/16W 200K 0.1% 0402; Part: RC0402BR-07200KL; Vendor: Yageo
U8 U10 U11 U15 U16 = DCDC_RT8096C_6: 1ST PART DESCRIPTION: RICHTEK DCDC RT8096C 1A 1.5M; part type: MB
C70 C200 = CAP_NP: 1ST PART DESCRIPTION: CAP 0.1uF X7R 6.3V 10%; Pin Names Rotate: True; Pin Names Visible: False; Pin Numbers Visible: False
C193 C208 C215 C217 C224 C225 C229 C232 C234 C237 C244 C247 C249 C266 C268 C270 = CAP_NP: 1ST PART DESCRIPTION: CAP 0.1uF X7R 6.3V 10%
C57 C194 C198 C205 C210 C220 C223 C254 = CAP_NP: 1ST PART DESCRIPTION: CAP 1uF X7R 6.3V 10%; Pin Names Rotate: True; Pin Names Visible: False; Pin Numbers Visible: False
C206 C214 C216 C264 C265 = CAP_NP: 1ST PART DESCRIPTION: CAP 10uF X7R 10V 10%; Pin Names Rotate: True; Pin Names Visible: False; Pin Numbers Visible: False
C209 C221 C227 C267 C269 C271 = CAP_NP: 1ST PART DESCRIPTION: CAP 10nF X7R 16V 10%
FB16-FB18 = FB: 1ST PART DESCRIPTION: MURATA BLM15AG121SN1 Ferrite Bead Z=120@100MHz 25%
R4 = R_10: 1ST PART DESCRIPTION: RESISTOR 240 OHM 1/16 1%; Pin Names Rotate: True; Pin Names Visible: False; Pin Numbers Visible: False
R40 = R_10: 1ST PART DESCRIPTION: RESISTOR 133R OHM 1/16 1%; 1ST PART FOOTPRINT: 0805
R86 R87 = R_MINI: 1ST PART DESCRIPTION: RESISTOR 10K OHM 1/16 1%
R89 = R_1: 1ST PART DESCRIPTION: RESISTOR 1K OHM 1/16 5%; 1ST PART FOOTPRINT: 0603; Pin Names Rotate: True; Pin Names Visible: False; Pin Numbers Visible: True
R101 = R_MINI: 1ST PART DESCRIPTION: RESISTOR 0 OHM 1/16 5%
U21 = X2100L
C52 C53 = CAP_NP_MINI: 1ST PART DESCRIPTION: CAP 15pF NPO 50V 10%; Pin Names Rotate: True; Pin Names Visible: False; Pin Numbers Visible: False
C130-C132 C135 C141 C151 C153 C252 C253 = CAP_NP_2
R18 R103 = R_MINI_7: 1ST PART DESCRIPTION: RESISTOR 1M OHM 1/16 5%; Pin Names Rotate: True; Pin Names Visible: False; Pin Numbers Visible: False
R90 R98-R100 = R_52: 1ST PART DESCRIPTION: RESISTOR 1.8K OHM 1/16 5%; Pin Names Rotate: True; Pin Names Visible: False; Pin Numbers Visible: True
R53 R61 R63 R64 R67 R70-R77 R93 R97 R102 = R_MINI: Pin Names Rotate: True; Pin Names Visible: False; Pin Numbers Visible: False
R94 = R_MINI: 1ST PART DESCRIPTION: Resistor-1M,+/-1%,1/16W-0402; Pin Names Rotate: True; Pin Names Visible: False; Pin Numbers Visible: False
U19 = XM25QH128A_0: 1ST PART DESCRIPTION: DOSILICON 2G bit SPI NAND FLASH DS35Q2GAIB
Y4 = CRYSTAL_4: 1ST PART DESCRIPTION: AKER CXAN-024000-AD09D40 +/-20PPM 9pF
C93 C94 C128 C129 C133 C134 C136-C140 C142 C143 C145-C150 C261 C263 C272 = CAP_NP_3: Pin Names Rotate: True; Pin Names Visible: False; Pin Numbers Visible: False
C256 C257 = CAP_NP: 1ST PART DESCRIPTION: CAP 4.7uF X7R 16V 20%; Pin Names Rotate: True; Pin Names Visible: False; Pin Numbers Visible: False
C258 C260 = CAP_NP: 1ST PART DESCRIPTION: CAP 10uF X7R 16V 20%; Pin Names Rotate: True; Pin Names Visible: False; Pin Numbers Visible: False
D2 = Diode_H_Zener_0
D3 = DIODE_PIN_5: 1ST PART DESCRIPTION: WILL WSB5546N schottky barrier diode; Pin Names Rotate: True; Pin Names Visible: False; Pin Numbers Visible: False
ESD15-ESD22 = 1_0.5KE100A
F1 = FUSE
J2 = CON12_0
J3 = CON16_0
L2 = INDUCTOR: 1ST PART DESCRIPTION: Inductor 2.2uH 3X3_SMD; Pin Names Rotate: True; Pin Names Visible: False; Pin Numbers Visible: False
L11-L14 = INDUCTOR: Pin Names Rotate: True; Pin Names Visible: False; Pin Numbers Visible: False
R11 R12 = R_0: 1ST PART DESCRIPTION: RESISTOR 510 OHM 1/16 5%; 1ST PART FOOTPRINT: R0603; Pin Names Rotate: True; Pin Names Visible: False; Pin Numbers Visible: True
TP14 TP31 TP36-TP43 = TEST_0
U4 = SOT-26_2
U12 = IC-8_1
U14 = SIT2515_1
Y2 = CRYSTAL_4

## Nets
AVDD14_RX: C11.2 C12.2 C13.2 C14.2 C15.2 C95.2 C96.2 C97.2 FB8.2 U1.J6(AVDD14_B) U1.L6(AVDD14_RX1) U1.N6(AVDD14_RX2) U1.R6(AVDD14_RX3) U1.U6(AVDD14_RX4)
AVDD14_SX: C35.2 C36.2 C37.2 C38.2 C98.2 C99.2 C100.2 FB9.2 U1.E17(AVDD14_SX1) U1.E18(AVDD14_SX2) U1.G14(AVDD14_SX3) U1.K12(AVDD14_LO)
AVDD14_TX: C1.2 C2.2 C3.2 C4.2 C5.2 C90.2 C91.2 C92.2 FB7.2 U1.E5(AVDD14_TX1) U1.E7(AVDD14_TX2) U1.E9(AVDD14_TX3) U1.E11(AVDD14_TX4) U1.E13(AVDD14_TX5)
AVDD18_RX: C16.2 C17.2 C18.2 C19.2 C20.2 C21.2 C22.2 C72.2 C73.2 C74.2 FB3.2 U1.E2(AVDD18_B1) U1.F2(AVDD18_B2) U1.J5(AVDD18_RX1) U1.L5(AVDD18_RX2) U1.N5(AVDD18_RX3) U1.R5(AVDD18_RX4) U1.U5(AVDD18_RX5)
AVDD18_TX: C6.2 C7.2 C8.2 C9.2 C10.2 C66.2 C67.2 C68.2 FB1.2 U1.F5(AVDD18_TX1) U1.F7(AVDD18_TX2) U1.F9(AVDD18_TX3) U1.F11(AVDD18_TX4) U1.F13(AVDD18_TX5)
AVDD18_XO: C39.2 C75.2 C76.2 C77.2 R48.2 U1.K17(AVDD18_XO)
DVDD14: C23.2 C24.2 C25.2 C26.2 C27.2 C40.2 C41.2 C42.2 C104.2 C105.2 C106.2 FB11.2 U1.K18(AVDD14_BBPLL) U1.L9(AVDD14_AD1) U1.N9(AVDD14_AD2) U1.N12(DVDD14_1) U1.N13(DVDD14_2) U1.N14(DVDD14_3) U1.R9(AVDD14_AD3) U1.U9(AVDD14_AD4)
DVDD18: C28.2 C29.2 C30.2 C31.2 C32.2 C33.2 C81.2 C82.2 C83.2 FB5.2 U1.G17(AVDD18_GPADC) U1.H15(AVDD18_BG) U1.K9(AVDD18_AD1) U1.L17(DVDD18) U1.M9(AVDD18_AD2) U1.P9(AVDD18_AD3) U1.P13(AVDD18_TOP) U1.T9(AVDD18_AD4)
DVDD_GPIO: C44.2 C45.2 C46.2 FB6.2 R31.1 U1.T17(DVDD_GPIO1) U1.T18(DVDD_GPIO2) U1.U11(DVDD_GPIO3)
GND: C1.1 C2.1 C3.1 C4.1 C5.1 C6.1 C7.1 C8.1 C9.1 C10.1 C11.1 C12.1 C13.1 C14.1 C15.1 C16.1 C17.1 C18.1 C19.1 C20.1 C21.1 C22.1 C23.1 C24.1 C25.1 C26.1 C27.1 C28.1 C29.1 C30.1 C31.1 C32.1 C33.1 C35.1 C36.1 C37.1 C38.1 C39.1 C40.1 C41.1 C42.1 C44.1 C45.1 C46.1 C48.1 C49.1 C50.1 C51.1 C52.2 C53.2 C57.2 C66.1 C67.1 C68.1 C70.1 C72.1 C73.1 C74.1 C75.1 C76.1 C77.1 C81.1 C82.1 C83.1 C84.1 C85.1 C87.2 C88.2 C90.1 C91.1 C92.1 C93.1 C94.1 C95.1 C96.1 C97.1 C98.1 C99.1 C100.1 C104.1 C105.1 C106.1 C116.2 C128.1 C129.1 C130.1 C131.1 C132.2 C135.2 C136.1 C137.1 C138.1 C139.1 C142.2 C143.1 C145.1 C146.1 C147.1 C148.2 C149.1 C150.2 C193.2 C194.2 C198.2 C200.2 C205.1 C206.2 C208.2 C209.2 C210.2 C214.2 C215.2 C216.2 C217.2 C220.1 C221.2 C223.2 C224.2 C227.2 C229.2 C232.2 C234.2 C237.2 C244.2 C247.2 C249.1 C252.1 C253.1 C254.2 C257.2 C258.2 C260.2 C261.1 C264.2 C265.2 C266.2 C267.2 C268.2 C269.2 C270.2 C271.2 C272.1 D2.2 ESD15.2(CATHODE) ESD16.2(CATHODE) ESD17.2(CATHODE) ESD18.2(CATHODE) ESD19.2(CATHODE) ESD20.2(CATHODE) ESD21.2(CATHODE) ESD22.2(CATHODE) H1.1 H2.1 H3.1 H4.1 J2.2 J2.11 J2.12 J3.8 J3.15 J3.16 R4.2 R12.2 R28.1 R40.2 R54.2 R56.1 R57.1 R63.1 R67.1 R73.2 R74.1 R77.2 R86.1 R89.1 R98.1 R99.1 R100.1 TP31.1(A) TP42.1(A) U1.A2(G_AVSS_RF1) U1.A3(G_AVSS_RF2) U1.A4(G_AVSS_RF3) U1.A5(G_AVSS_RF4) U1.A6(TX4) U1.A7(G_AVSS_RF5) U1.A8(TX3) U1.A9(G_AVSS_RF6) U1.A11(G_AVSS_RF7) U1.A13(G_AVSS_RF8) U1.A14(G_AVSS_RF9) U1.A15(G_AVSS_RF10) U1.A16(LO_SYNCI) U1.A17(G_AVSS_RF11) U1.A18(G_AVSS_RF12) U1.B1(G_AVSS_RF13) U1.B2(G_AVSS_RF14) U1.B3(G_AVSS_RF15) U1.B4(G_AVSS_RF16) U1.B5(G_AVSS_RF17) U1.B7(G_AVSS_RF18) U1.B9(G_AVSS_RF19) U1.B11(G_AVSS_RF20) U1.B13(G_AVSS_RF21) U1.B14(G_AVSS_RF22) U1.B15(G_AVSS_RF23) U1.B16(G_AVSS_RF24) U1.B17(G_AVSS_RF25) U1.B18(G_AVSS_RF26) U1.B19(G_AVSS_RF27) U1.C1(G_AVSS_RF28) U1.C2(LO_SYNCO2) U1.C3(G_AVSS_RF29) U1.C5(G_AVSS_RF30) U1.C7(G_AVSS_RF31) U1.C9(G_AVSS_RF32) U1.C11(G_AVSS_RF33) U1.C13(G_AVSS_RF34) U1.C14(G_AVSS_RF35) U1.C15(G_AVSS_RF36) U1.C16(G_AVSS_RF37) U1.C17(G_AVSS_RF38) U1.C18(G_AVSS_RF39) U1.C19(LO_SYNCO) U1.D1(G_AVSS_RF40) U1.D2(G_AVSS_RF41) U1.D3(G_AVSS_RF42) U1.D5(G_AVSS_RF43) U1.D7(G_AVSS_RF44) U1.D9(G_AVSS_RF45) U1.D11(G_AVSS_RF46) U1.D13(G_AVSS_RF47) U1.D16(G_AVSS_RF48) U1.D17(G_AVSS_RF49) U1.D18(G_AVSS_RF50) U1.D19(G_AVSS_RF51) U1.E1(G_AVSS_RF52) U1.E3(G_AVSS_RF53) U1.E19(ACT_SX) U1.F1(G_AVSS_RF54) U1.F3(G_AVSS_RF55) U1.F14(G_AVSS_RF56) U1.F17(G_AVSS_RF57) U1.F18(G_AVSS_RF58) U1.F19(G_AVSS_RF59) U1.G1(G_AVSS_RF60) U1.G2(G_AVSS_RF61) U1.G3(G_AVSS_RF62) U1.G5(G_AVSS_RF63) U1.G7(G_AVSS_RF64) U1.G9(G_AVSS_RF65) U1.G11(G_AVSS_RF66) U1.G13(G_AVSS_RF67) U1.G19(G_AVSS43) U1.H1(G_AVSS_RF68) U1.H2(G_AVSS_RF69) U1.H3(G_AVSS_RF70) U1.H13(G_AVSS_RF71) U1.H14(G_AVSS42) U1.H16(G_AVSS41) U1.H17(G_AVSS40) U1.H19(ACT_BBPLL) U1.J1(G_AVSS_RF72) U1.J2(G_AVSS_RF73) U1.J3(G_AVSS_RF74) U1.J4(G_AVSS_RF75) U1.J7(G_AVSS_RF76) U1.J16(G_AVSS39) U1.J17(G_AVSS38) U1.J18(XTAL_SYNCI) U1.K10(G_AVSS37) U1.K11(G_AVSS_RF77) U1.K16(XTAL_SYNCO) U1.L1(G_AVSS_RF112) U1.L2(G_AVSS_RF111) U1.L3(G_AVSS_RF110) U1.L4(G_AVSS_RF109) U1.L7(G_AVSS_RF108) U1.L10(G_AVSS36) U1.L11(G_AVSS_RF107) U1.L12(G_AVSS_RF106) U1.L13(G_DVSS25) U1.L14(G_AVSS35) U1.L16(G_AVSS34) U1.M10(G_AVSS33) U1.M11(G_DVSS24) U1.M12(G_DVSS23) U1.M13(G_DVSS22) U1.M14(G_DVSS21) U1.M17(G_DVSS20) U1.N1(G_AVSS_RF105) U1.N2(G_AVSS_RF104) U1.N3(G_AVSS_RF103) U1.N4(G_AVSS_RF102) U1.N7(G_AVSS_RF101) U1.N10(G_AVSS32) U1.N11(G_DVSS19) U1.N17(G_DVSS18) U1.P10(G_AVSS31) U1.P11(G_DVSS17) U1.P12(G_DVSS16) U1.P16(G_DVSS15) U1.P17(G_DVSS14) U1.R1(G_AVSS_RF100) U1.R2(G_AVSS_RF99) U1.R3(G_AVSS_RF98) U1.R4(G_AVSS_RF97) U1.R7(G_AVSS_RF96) U1.R10(G_AVSS30) U1.R11(G_DVSS13) U1.R14(G_AVSS29) U1.R15(ACT_32K) U1.R16(G_DVSS12) U1.R17(G_DVSS11) U1.T10(G_AVSS28) U1.T11(G_DVSS10) U1.T15(G_DVSS9) U1.T19(G_DVSS8) U1.U1(G_AVSS_RF95) U1.U2(G_AVSS_RF94) U1.U3(G_AVSS_RF93) U1.U4(G_AVSS_RF92) U1.U7(G_AVSS_RF91) U1.U10(G_AVSS27) U1.U15(FSYNCI) U1.U17(G_DVSS7) U1.U18(G_DVSS6) U1.U19(G_DVSS5) U1.V1(G_AVSS_RF90) U1.V2(G_AVSS_RF89) U1.V3(G_AVSS_RF88) U1.V4(G_AVSS_RF87) U1.V5(G_AVSS_RF86) U1.V6(G_AVSS_RF85) U1.V7(G_AVSS_RF84) U1.V8(PGAP_TP) U1.V9(AD_EXTCLK) U1.V10(G_DVSS4) U1.V11(G_DVSS3) U1.V16(FSYNCO) U1.V18(SCAN_EN_TOP) U1.W2(G_AVSS_RF83) U1.W3(G_AVSS_RF82) U1.W4(G_AVSS_RF81) U1.W5(G_AVSS_RF80) U1.W6(G_AVSS_RF79) U1.W7(G_AVSS_RF78) U1.W8(PGAN_TP) U1.W9(G_AVSS26) U1.W10(G_DVSS2) U1.W15(TestMode) U1.W18(G_DVSS1) U4.3(GND) U8.2(GND) U10.2(GND) U11.2(GND) U12.2(GND) U14.10(GND) U15.2(GND) U16.2(GND) U19.4(VSS) U21.C15(DDR_VSSA) U21.D8(VSS_0) U21.D10(VSS_1) U21.D12(VSS_2) U21.D14(VSS_3) U21.E9(VSS_4) U21.E17(VSS_5) U21.F8(VSS_6) U21.F10(VSS_7) U21.F12(VSS_8) U21.F14(VSS_9) U21.F16(VSS_10) U21.G13(VSS_11) U21.G17(VSS_12) U21.H8(VSS_13) U21.H12(VSS_14) U21.J7(VSS_15) U21.J9(VSS_16) U21.J17(VSS_17) U21.K10(VSS_18) U21.K12(VSS_19) U21.K16(VSS_20) U21.L5(VSS_RTC) U21.L11(VSS_21) U21.L13(VSS_22) U21.L15(VSS_23) U21.L17(VSS_24) U21.M4(PLL_AVSS) U21.M6(PLL_VSS) U21.M8(VSS_25) U21.M12(VSS_26) U21.N7(VSS_27) U21.N11(VSS_28) U21.P8(VSS_29) U21.P12(VSS_30) U21.P18(DSI_AVSS) U21.R7(VSS_31) U21.R9(VSS_32) U21.R11(VSS_33) U21.T10(VSS_34) U21.T14(VSS_35) U21.T16(VSS_36) U21.T18(CSI_AVSS) U21.U9(VSS_37) U21.U13(VSS_38) U21.U15(VSS_39) U21.U17(VSS_40) U21.V8(USB_AVSS) U21.W7(SADC_AVSS) U21.W9(CODEC_AVSS) Y1.2 Y1.4 Y2.2 Y2.4 Y4.2 Y4.4
VDD12_MEM: C93.2 C94.2 C151.2 C214.1 C215.1 C223.1 C225.1 C227.1 C266.1 C267.1 L14.1 R64.2 R87.2 U21.A9(VDDMEM_0) U21.A11(VDDMEM_1) U21.B10(VDDMEM_2) U21.C9(VDDMEM_3) U21.C11(VDDMEM_4) U21.D16(VDDMEM_5) U21.E11(VDDMEM_6) U21.E13(VDDMEM_7) U21.E15(VDDMEM_8)
VIN_12V: C260.1 C261.2 D3.1 R102.1 U4.4(IN)
BOOT_SEL0: R98.2 U21.P6(BOOT_SEL0/PE25)
BOOT_SEL1: J3.3 R99.2 TP36.1(A) U21.N5(BOOT_SEL1/PE26)
BOOT_SEL2: R100.2 U21.P4(BOOT_SEL2/PE27)
BUCK_1V8: C138.2 C140.2 C146.2 C194.1 C229.1 C232.1 C234.1 C247.1 FB16.1 FB17.2 J3.4 L12.1 R75.2 R83.1 R93.2 R94.2 TP43.1(A) U8.1(EN) U16.1(EN) U21.AA7(USB_AVD18) U21.AB10(CODEC_AVDD) U21.AC3(SADC_AVDD) U21.B12(DDR_VDD1_0) U21.C13(DDR_VDD1_1) U21.H2(VDDIO_RTC) U21.K8(VDDIO_0) U21.L7(VDDIO_1) U21.N17(VDDIO18_0) U21.P20(DSI_AVD18) U21.R17(VDDIO18_1) U21.T8(VDDIO18_CIM) U21.T20(CSI_AVD18)
BUCK_3V3: C57.1 C139.2 C141.2 C143.2 C193.1 C237.1 C254.1 FB12.1 FB13.1 L11.1 R53.2 R97.2 R101.2 R103.1 U11.1(EN) U19.8(VCC) U21.M16(VDDIO33_0) U21.P16(VDDIO33_1) U21.U7(VDDIO33_CIM) U21.Y8(USB_AVD33)
BUCK_CORE: C147.2 C149.2 C153.2 C206.1 C208.1 C209.1 C216.1 C217.1 C221.1 C244.1 C249.2 C268.1 C269.1 C270.1 C271.1 FB18.2 L13.1 R61.2 U21.AB6(USB_AVD09) U21.G9(VDD_0) U21.G11(VDD_1) U21.G15(VDD_2) U21.H10(VDD_3) U21.H14(VDD_4) U21.H16(VDD_5) U21.J1(VDD_RTC) U21.J11(VDD_6) U21.J13(VDD_7) U21.J15(VDD_8) U21.K14(VDD_9) U21.L9(VDD_10) U21.M10(VDD_11) U21.M14(VDD_12) U21.N9(VDD_13) U21.N13(VDD_14) U21.N15(VDD_15) U21.N19(DSI_AVD09) U21.P10(VDD_16) U21.P14(VDD_18) U21.R13(VDD_19) U21.R15(VDD_20) U21.R19(CSI_AVD09)
CANH: C133.2 ESD15.1(ANODE) J2.10 R71.2 U12.7(CANH)
CANL: C134.1 ESD16.1(ANODE) J2.9 R72.1 U12.6(CANL)
CASCADE: R57.2 U1.P15(CASCADE)
CH_1V4: C86.2 C87.1 C88.1 FB7.1 FB8.1 FB9.1 FB11.1 L5.2 R51.1
CH_1V8: C116.1 FB1.1 FB3.1 FB5.1 FB6.1 R48.1 R83.2
CKN_PHY: U1.N18(PHY_CKN) U21.V22(RX_CLKN0)
CKP_PHY: U1.N19(PHY_CKP) U21.U21(RX_CLKP0)
D0N_PHY: U1.L19(PHY_D0N) U21.R21(RX_DATAN0)
D0P_PHY: U1.L18(PHY_D0P) U21.R23(RX_DATAP0)
D1N_PHY: U1.M19(PHY_D1N) U21.U23(RX_DATAN1)
D1P_PHY: U1.M18(PHY_D1P) U21.T22(RX_DATAP1)
D2N_PHY: U1.P18(PHY_D2N) U21.W23(RX_DATAN2)
D2P_PHY: U1.P19(PHY_D2P) U21.W21(RX_DATAP2)
D3N_PHY: U1.R18(PHY_D3N) U21.AA23(RX_DATAN3)
D3P_PHY: U1.R19(PHY_D3P) U21.Y22(RX_DATAP3)
DDR_VREF: C224.1 C225.2 R86.2 R87.1 U21.A13(VREF)
EXCLKI: C52.1 R18.1 U21.N1(EXCLK_XI) Y4.1
EXCLKO: R18.2 R90.2 U21.N3(EXCLK_XO)
EXT_12V: C272.2 F1.1 J2.1 TP14.1(A)
INT: TP28.1(A) U1.T14(INTERRUPT)
MSC2_CLK: J3.14 U21.W13(MSC2_CLK/PWM2/TCU1_IN0/PE00)
MSC2_CMD: J3.12 U21.W11(MSC2_CMD/PWM3/TCU1_IN1/PE01)
MSC2_D0: J3.9 U21.Y10(MSC2_D0/PWM4/TCU2_IN0/PE02)
MSC2_D1: J3.11 U21.V10(MSC2_D1/PWM5/TCU2_IN1/PE03)
MSC2_D2: J3.10 U21.Y12(MSC2_D2/PWM6/TCU3_IN0/PE04)
MSC2_D3: J3.13 U21.V12(MSC2_D3/PWM7/TCU3_IN1/PE05)
PB26/RST: R70.1 U14.19(RST) U21.G19(SD10/LCD_HSYNC/SLCD_WR/PB26)
PB27/INT: U14.13(INT) U21.C19(SD11/LCD_DE/SLCD_TE/PB27)
PB28/CS: U14.18(CS) U21.F20(SD12/SSI0_CE0_N/UART8_RXD/PB28)
PB29/MISO: U14.17(SO) U21.F18(SD13/SSI0_DR/UART8_TXD/PB29)
PB30/MOSI: U14.16(SI) U21.E19(SD14/SSI0_DT/UART9_RXD/PB30)
PB31/CLK: U14.14(SCK) U21.D18(SD15/SSI0_CLK/UART9_TXD/PB31)
PC01/BEEP: ESD20.1(ANODE) J2.5 U21.Y20(PWM1/TCU0_IN1/RMII0_PHY_CLK/I2S1_RX_MCLK/UART7_RXD/PC01)
PC02/LED_L: ESD22.1(ANODE) J2.3 U21.AC17(PWM2/TCU1_IN0/RMII0_TXD0/I2S1_RX_BCLK/UART7_TXD/PC02)
PC03/LED_R: ESD21.1(ANODE) J2.4 U21.AB16(PWM3/TCU1_IN1/RMII0_TXD1/I2S1_RX_LRCK/SCC_SCK/PC03)
PC04/BACK_IN: ESD17.1(ANODE) J2.8 U21.Y16(PWM4/TCU2_IN0/I2S1_RX_DATA/SCC_SDA/PC04)
PD05/CH_RST: C51.2 R31.2 U1.V19(SRSTB) U21.B8(I2C5_SDA/PCM_SYNC/PD05)
POR_BYPASS: R56.2 U1.P14(POR_BYPASS)
PPRST_N: C252.2 R93.1 U21.K6(PPRST_N)
RX1: RX1.1 U1.K1(RX1)
RX2: RX2.1 U1.M1(RX2)
RX3: RX3.1 U1.P1(RX3)
RX4: RX4.1 U1.T1(RX4)
RXCAN: U12.4(RXD) U14.2(RXCAN)
SFC0_CE_N: R103.2 U19.1(CS_N) U21.AB12(SFC0_CE_N/SSI1_DT/PE17)
SFC0_CLK: U19.6(CLK) U21.AC13(SFC0_CLK/SSI1_CLK/PE16)
SFC0_DQ0: U19.5(DI(DQ0)) U21.AA13(SFC0_DQ0/SSI1_DR/PE18)
SFC0_DQ1: U19.2(DO(DQ1)) U21.AA15(SFC0_DQ1/I2C2_SCK/PE19)
SFC0_DQ2: U19.3(WP_N(DQ2)) U21.AC15(SFC0_DQ2_WP_N/I2C2_SDA/PE20)
SFC0_DQ3_HOLD_N: U19.7(HOLD_N(DQ3)) U21.AB14(SFC0_DQ3_HOLD_N/SSI1_CE0_N/PE21)
SPI_CLK: U1.W17(SPI_CLK) U21.G1(MSC0_CLK/SFC0_CLK/SSI1_CLK/PD17)
SPI_CS: U1.U16(SPI_CS) U21.E3(MSC0_D3/SFC0_DQ3_HOLD_N/SSI1_CE0_N/PD22)
SPI_MISO: U1.V17(SPI_MISO) U21.E1(MSC0_D0/SFC0_DQ0/SSI1_DR/PD19)
SPI_MOSI: U1.W16(SPI_MOSI) U21.G3(MSC0_CMD/SFC0_CE_N/SSI1_DT/PD18)
TX1: TX3.1 U1.A12(TX1)
TX2: TX2.1 U1.A10(TX2)
TXCAN: U12.1(TXD) U14.1(TXCAN)
UART2_RXD: J3.1 TP37.1(A) U21.B4(UART2_RXD/I2C3_SCK/PWM0/TCU0_IN0/PD30)
UART2_TXD: J3.2 TP38.1(A) U21.C5(UART2_TXD/I2C3_SDA/PWM1/TCU0_IN1/PD31)
UART3_RXD: ESD18.1(ANODE) J2.7 R97.1 U21.B16(UART3_RXD/I2C4_SCK/PC25)
UART3_TXD: ESD19.1(ANODE) J2.6 U21.A17(UART3_TXD/I2C4_SDA/PC26)
USB_DN: J3.6 TP40.1(A) U21.AA5(USB_DM0)
USB_DP: J3.7 TP41.1(A) U21.AC5(USB_DP0)
VSYS: C84.2 C85.2 C136.2 C142.1 C145.2 C148.1 C150.1 C256.1 C257.1 C258.1 J3.5 L2.2 R11.1 R50.2 R76.1 TP39.1(A) U8.4(VIN) U10.4(VIN) U11.4(VIN) U12.3(VCC) U15.4(VIN) U16.4(VIN)
WKUP_N: C253.2 R94.1 U21.L3(WKUP_N/PE31)
N2439824: C86.1 R51.2 R54.1 U10.5(FB)
N2440064: L5.1 U10.3(SW)
N2464554: C48.2 U1.J19(XTALI) Y1.1
N2465035: C49.2 U1.K19(XTALO) Y1.3
N2479306: R28.2 U1.G18(BGR)
N2558545: C50.2 U1.H18(DCT_GPADC)
N2669126: R50.1 U10.1(EN)
N2735799: C128.2 C129.2 FB12.2 R70.2 U14.20(VDD)
N2735943: C131.2 U14.9(OSC1) Y2.1
N2735967: C130.2 U14.8(OSC2) Y2.3
N2736087: C133.1 C134.2 C135.1
N2736303: C132.1 R71.1 R72.2
N2736527: R73.1 U12.8(STB)
N2736623: C137.2 FB13.2 U12.5(VIO)
N2737540: C141.1 R53.1 R77.1 U8.5(FB)
N2737548: R76.2 U15.1(EN)
N2737552: C140.1 R74.2 R75.1 U15.5(FB)
N2737610: L12.2 U15.3(SW)
N2737826: L11.2 U8.3(SW)
N2738138: D2.1 D3.2 F1.2
N2739230: C153.1 R61.1 R63.2 U16.5(FB)
N2739292: L13.2 U16.3(SW)
N2739406: C151.1 R64.1 R67.2 U11.5(FB)
N2739468: L14.2 U11.3(SW)
N16675046: C53.1 R90.1 Y4.3
N16679120: C205.2 C264.1 FB17.1 U21.L1(PLL_AVDD)
N16679422: R40.1 U21.AC7(USB_BIAS)
N16679836: C198.1 R101.1 U21.T12(VDDIO33_SD)
N16679980: C220.2 C265.1 FB18.1 U21.M2(PLL_VDD)
N16679984: C200.1 FB16.2 U21.A15(DDRPLL_VCCA)
N16680310: R4.1 U21.B14(ZQ)
N16680330: R89.2 U21.A5(AVDEFUSE)
N16680520: C210.1 U21.U11(VDDIO18_SD)
N16681692: C70.2 U21.AC9(CODEC_VCM)
N16703806: C263.1 L2.1 U4.5(LX)
N16704000: C256.2 R11.2 R12.1 U4.1(FB)
N16708145: C263.2 U4.6(BS)
N16719733: R102.2 U4.2(EN)

Not connected (* = marked no-connect by the designer): U1 A1(DMY1)* A19(DMY2)* R12(ADC_D3)* R13(ADC_D8)* T12(ADC_D2)* T13(ADC_D7)* U12(ADC_D1)* U13(ADC_D6)* U14(ADC_D11)* V12(ADC_D0)* V13(ADC_D5)* V14(ADC_D10)* V15(GPIO_RSV)* W1(DMY3)* W11(ADC_CLK)* W12(ADC_VALID)* W13(ADC_D4)* W14(ADC_D9)* W19(DMY4)*; U14 3(CLKOUT)* 4(TX0RTS)* 5(TX1RTS)* 6(NC1)* 7(TX2RTS)* 11(RX1BF)* 12(RX0BF)* 15(NC2)*; U21 A1(SDIO_CMD/SSI0_DT/PD09)* A3(SDIO_D3/SSI0_CE0_N/PD13)* A7(UART3_TXD/PCM_DO/TCK/PD03)* A19(SD0/LCD_D16/PB16)* A21(SD2/LCD_D18/PB18)* A23(SA11/LCD_D11/SLCD_D11/PB11)* AA1(CIM_VIC_D0/UART4_CTS_N/I2S3_TX_MCLK/PA00)* AA3(AUX4)* AA9(CODEC_MICLN)* AA11(CODEC_HPOUTP)* AA17(PWM5/TCU2_IN1/I2S1_TX_BCLK/UART5_RXD/PC05)* AA19(PWM8/TCU4_IN0/I2S1_TX_MCLK/UART6_TXD/PC08)* AA21(RX_CLKP1)* AB2(AUX1)* AB4(AUX5)* AB8(CODEC_MICLP)* AB18(PWM14/TCU7_IN0/SPDIF_OUT/I2C0_SDA/PC14)* AB20(PWM15/TCU7_IN1/RMII0_REF_CLK/CIM_VIC_MCLK/PC15)* AB22(RX_CLKN1)* AC1(AUX3)* AC11(CODEC_HPOUTN)* AC19(PWM9/TCU4_IN1/SSI1_CE0_N/UART4_CTS_N/PC09)* AC21(PWM12/TCU6_IN0/RMII0_MDC/SSI1_CLK/UART4_TXD/PC12)* AC23(PWM13/TCU6_IN1/RMII0_MDIO/SPDIF_IN/I2C0_SCK/PC13)* B2(SDIO_D1/I2C1_SCK/PD11)* B6(UART3_RXD/PCM_CLK/TDI/PD02)* B18(UART3_RTS_N/I2C5_SDA/PC28)* B20(SD8/LCD_PCLK/SLCD_CE_N/PB24)* B22(SA12/LCD_D12/SLCD_D12/PB12)* C1(SDIO_CLK/SSI0_CLK/PD08)* C3(SDIO_D0/SSI0_DR/PD10)* C7(I2C5_SCK/PCM_DI/TMS/PD04)* C17(UART3_CTS_N/I2C5_SCK/PC27)* C21(RD_N/LCD_D13/SLCD_D13/PB13)* C23(SD5/LCD_D21/PB21)* D2(MSC0_D2/SFC0_DQ2_WP_N/I2C2_SDA/PD21)* D4(SDIO_D2/I2C1_SDA/PD12)* D6(UART3_RTS_N/I2C4_SDA/TDO/PD01)* D20(SD9/LCD_VSYNC/SLCD_DC/PB25)* D22(WE_N/LCD_D14/SLCD_D14/PB14)* E5(MSC0_D7/SFC1_DQ3_HOLD_N/UART0_RTS_N/PD26)* E7(UART3_CTS_N/I2C4_SCK/PD00)* E21(SD7/LCD_D23/I2C2_SDA/PB23)* E23(SA8/LCD_D8/SLCD_D8/PB08)* F2(MSC0_D1/SFC0_DQ1/I2C2_SCK/PD20)* F4(MSC0_D6/SFC1_DQ2_WP_N/UART0_CTS_N/PD25)* F6(TRST)* F22(SA9/LCD_D9/SLCD_D9/PB09)* G5(MSC0_D4/SFC1_DQ0/UART0_RXD/PD23)* G21(SD6/LCD_D22/I2C2_SCK/PB22)* G23(SA3/LCD_D3/SLCD_D3/PB03)* H4(MSC0_D5/SFC1_DQ1/UART0_TXD/PD24)* H6(EXCLK/CIM_VIC_MCLK/PE24)* H18(SD4/LCD_D20/PB20)* H20(WAIT_N/LCD_D15/SLCD_D15/PB15)* H22(SA4/LCD_D4/SLCD_D4/PB04)* J3(PWRON)* J5(RTC32K/PE23)* J19(SD3/LCD_D19/PB19)* J21(SA6/LCD_D6/SLCD_D6/PB06)* J23(SA1/LCD_D1/SLCD_D1/PB01)* K2(OSC32_XI)* K4(OSC32_XO)* K18(SA10/LCD_D10/SLCD_D10/PB10)* K20(SD1/LCD_D17/PB17)* K22(SA2/LCD_D2/SLCD_D2/PB02)* L19(SA5/LCD_D5/SLCD_D5/PB05)* L21(TX_DATAP0)* L23(TX_DATAN0)* M18(SA7/LCD_D7/SLCD_D7/PB07)* M20(SA0/LCD_D0/SLCD_D0/PB00)* M22(TX_DATAP1)* N21(TX_CLKP)* N23(TX_DATAN1)* P2(I2C3_SDA/I2S2_RX_BCLK/PA17)* P22(TX_CLKN)* R1(I2C3_SCK/I2S3_TX_BCLK/PA16)* R3(CIM_VIC_VSYNC/I2S2_RX_DATA3/PA13)* R5(CIM_VIC_HSYNC/I2S2_RX_DATA2/PA12)* T2(CIM_VIC_PCLK/PA14)* T4(CIM_EXPOSURE/PA15)* T6(VIC_D10/I2S2_RX_DATA0/PA10)* U1(VIC_D8/UART7_RXD/PA08)* U3(VIC_D9/UART7_TXD/I2S2_RX_LRCK/PA09)* U5(VIC_D11/I2S2_RX_DATA1/PA11)* U19(DMIC_IN2/UART1_RXD/I2C1_SCK/NEMC_CS1_N/PC23)* V2(CIM_VIC_D7/UART6_TXD/I2S2_RX_MCLK/PA07)* V4(CIM_VIC_D6/UART6_RXD/I2S3_TX_DATA3/PA06)* V6(CIM_VIC_D5/UART5_TXD/I2S3_TX_DATA2/PA05)* V14(PWM6/TCU3_IN0/RMII0_RXD0/I2S1_TX_LRCK/UART5_TXD/PC06)* V16(PWM11/TCU5_IN1/RMII0_CRS_DV/SSI1_DT/UART4_RXD/PC11)* V18(DMIC_IN0/UART1_CTS_N/PC21)* V20(DMIC_IN3/UART1_TXD/I2C1_SDA/NEMC_CS2_N/PC24)* W1(CIM_VIC_D2/UART4_RXD/I2S3_TX_LRCK/PA02)* W3(CIM_VIC_D3/UART4_TXD/I2S3_TX_DATA0/PA03)* W5(CIM_VIC_D4/UART5_RXD/I2S3_TX_DATA1/PA04)* W15(PWM7/TCU3_IN1/RMII0_RXD1/I2S1_TX_DATA/UART6_RXD/PC07)* W17(PWM0/TCU0_IN0/PC00)* W19(DMIC_IN1/UART1_RTS_N/PC22)* Y2(CIM_VIC_D1/UART4_RTS_N/PA01)* Y4(AUX2)* Y6(AUX0)* Y14(PWM10/TCU5_IN0/RMII0_TX_EN/SSI1_DR/UART4_RTS_N/PC10)* Y18(DMIC_CLK/PC20)*

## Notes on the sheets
sheet 1
- SenardMicro
sheet 2
- SenardMicro
sheet 3
- Vfb=0.6V
- SenardMicro
sheet 4
- BOOT_SEL1=1 FOR USB
- NOR FLASH
- debug
- SenardMicro
sheet 5
- SenardMicro
sheet 6
- Vfb=0.6V
- Vfb=0.6V
- debug
- Vfb=0.6V
- Vfb=0.6V
- Vfb=0.6V
- SenardMicro
